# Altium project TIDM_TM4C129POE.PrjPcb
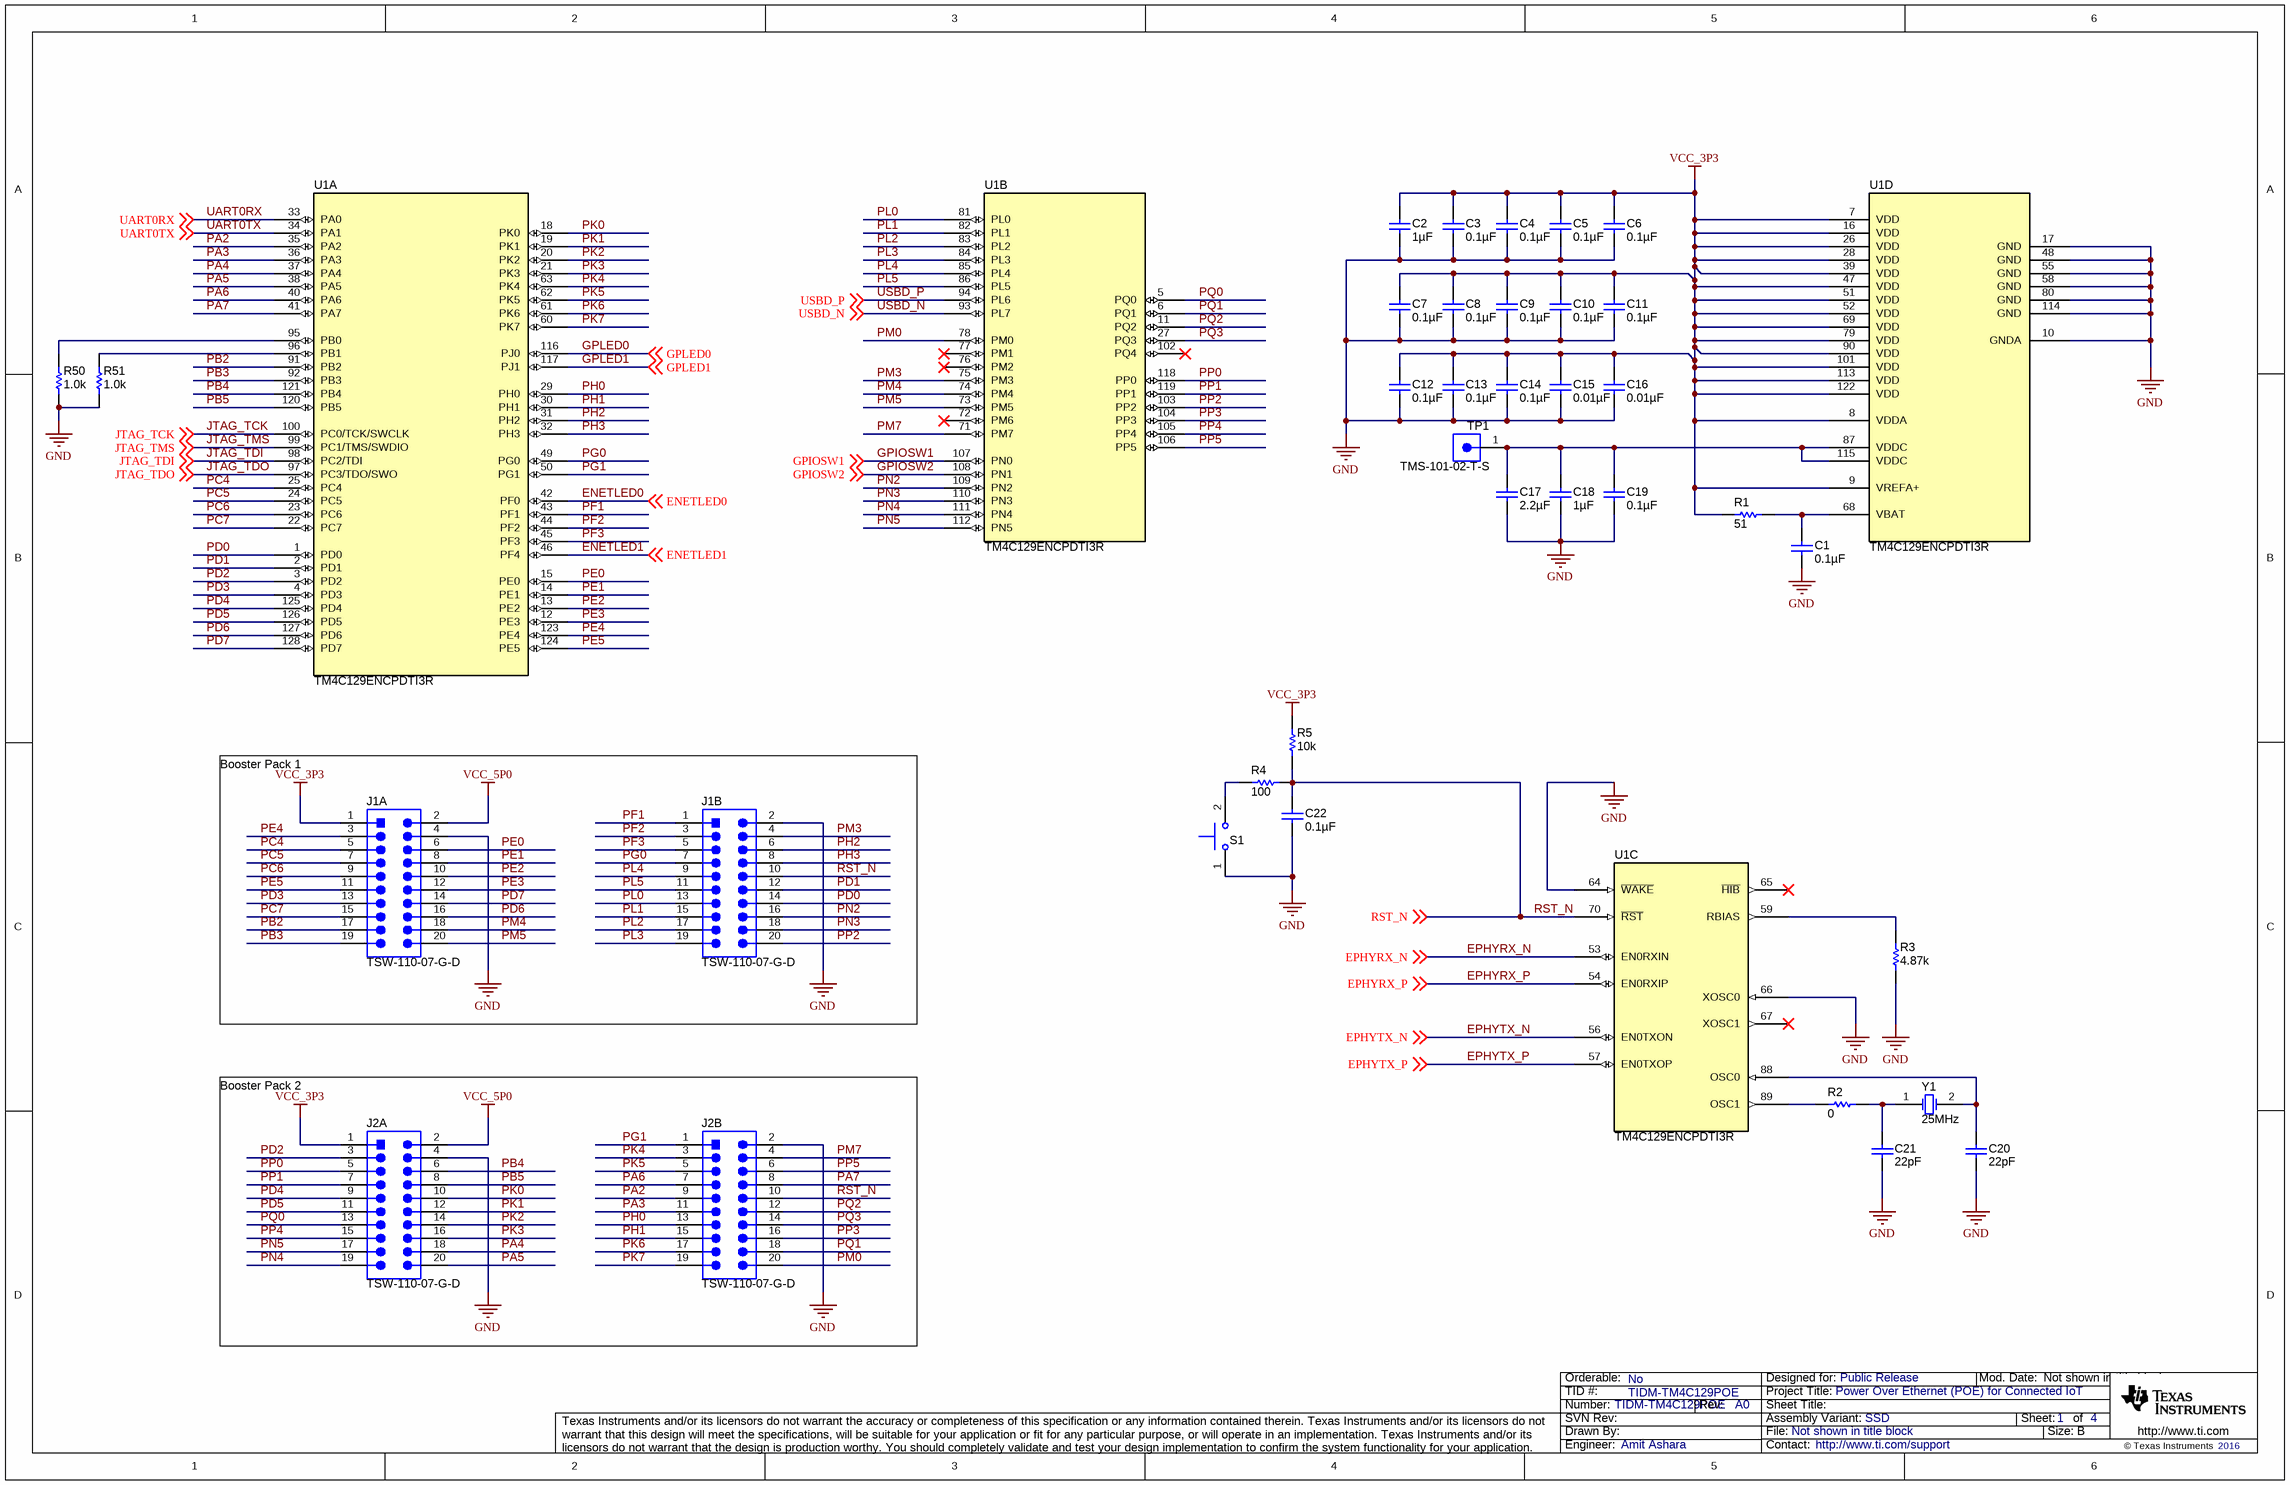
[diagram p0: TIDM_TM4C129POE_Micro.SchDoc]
VariantName: SSD; TID: TIDM-TM4C129POE; TechSupport: http://www.ti.com/support; SCH_Rev: A0; PRJ_Title: Power Over Ethernet (POE) for Connected IoT; PRJ_Number: TIDM-TM4C129POE; PRJ_Engineer: Amit Ashara; PRJ_Customer: Public Release; PCB_Rev: A0; PCB_Layout: Amit Ashara; EVM_Orderable: No; CopyrightYear: 2016
4 sheets, 160 parts. Net scope: global (net labels, ports and power ports of the same name join across sheets).
Board file: TIDM_TM4C129POE.PcbDoc
Sheets:
  TIDM_TM4C129POE_Micro.SchDoc
  TIDM_TM4C129POE_Connector.SchDoc
  TIDM_TM4C129POE_Ethernet.SchDoc
  TIDM_TM4C129POE_PowerStage.SchDoc

## Sheet TIDM_TM4C129POE_Micro.SchDoc
size 431 x 279 mm; Date: Not shown in title block; ApprovedBy: Not shown in title block; CheckedBy: Not shown in title block; Author: Not shown in title block; CompanyName: Not shown in title block; Engineer: Not shown in title block; Organization: Not shown in title block; Address1: Not shown in title block; Address2: Not shown in title block; Address3: Not shown in title block; Address4: Not shown in title block; DocumentNumber: 1; Revision: Use project parameter SCH_Rev; SheetNumber: 1; SheetTotal: 4; PageSetup: Record=PageOptions¦CenterHorizontal=True¦CenterVertical=True¦PrintScale=1.00¦XCorrection=1.00¦YCorrection=1.00¦PrintKind=0¦BorderSize=5000000¦LeftOffset=0¦BottomOffset=0¦Orientation=2¦PaperLength=1000¦PaperWidth=1000¦Scale=100¦PaperSource=15¦PrintQuality=600¦MediaType=1¦DitherType=10¦PaperKind=Letter¦PrintScaleMode=1

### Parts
C1  ValueDisplayed: 0.1µF  [0402]  (hidden comment: GRM155R71C104KA88D)
C2  ValueDisplayed: 1µF  [0402]  (hidden comment: C1005X5R1C105K050BC)
C3  ValueDisplayed: 0.1µF  [0402]  (hidden comment: GRM155R71C104KA88D)
C4  ValueDisplayed: 0.1µF  [0402]  (hidden comment: GRM155R71C104KA88D)
C5  ValueDisplayed: 0.1µF  [0402]  (hidden comment: GRM155R71C104KA88D)
C6  ValueDisplayed: 0.1µF  [0402]  (hidden comment: GRM155R71C104KA88D)
C7  ValueDisplayed: 0.1µF  [0402]  (hidden comment: GRM155R71C104KA88D)
C8  ValueDisplayed: 0.1µF  [0402]  (hidden comment: GRM155R71C104KA88D)
C9  ValueDisplayed: 0.1µF  [0402]  (hidden comment: GRM155R71C104KA88D)
C10  ValueDisplayed: 0.1µF  [0402]  (hidden comment: GRM155R71C104KA88D)
C11  ValueDisplayed: 0.1µF  [0402]  (hidden comment: GRM155R71C104KA88D)
C12  ValueDisplayed: 0.1µF  [0402]  (hidden comment: GRM155R71C104KA88D)
C13  ValueDisplayed: 0.1µF  [0402]  (hidden comment: GRM155R71C104KA88D)
C14  ValueDisplayed: 0.1µF  [0402]  (hidden comment: GRM155R71C104KA88D)
C15  ValueDisplayed: 0.01µF  [0402]  (hidden comment: GRM155R71C103KA01D)
C16  ValueDisplayed: 0.01µF  [0402]  (hidden comment: GRM155R71C103KA01D)
C17  ValueDisplayed: 2.2µF  [0402]  (hidden comment: GRM155R61C225KE11D)
C18  ValueDisplayed: 1µF  [0402]  (hidden comment: C1005X5R1C105K050BC)
C19  ValueDisplayed: 0.1µF  [0402]  (hidden comment: GRM155R71C104KA88D)
C20  ValueDisplayed: 22pF  [0402]  (hidden comment: C1005C0G1H220J050BA)
C21  ValueDisplayed: 22pF  [0402]  (hidden comment: C1005C0G1H220J050BA)
C22  ValueDisplayed: 0.1µF  [0603]  (hidden comment: C0603C104J3RAC)
J1A  TSW-110-07-G-D  [TSW-110-07-G-D]
J1B  TSW-110-07-G-D  [TSW-110-07-G-D]
J2A  TSW-110-07-G-D  [TSW-110-07-G-D]
J2B  TSW-110-07-G-D  [TSW-110-07-G-D]
R1  ValueDisplayed: 51  [0603]  (hidden comment: CRCW060351R0JNEA)
R2  ValueDisplayed: 0  [0402]  (hidden comment: ERJ-2GE0R00X)
R3  ValueDisplayed: 4.87k  [0603]  (hidden comment: CRCW06034K87FKEA)
R4  ValueDisplayed: 100  [0402]  (hidden comment: CRCW0402100RJNED)
R5  ValueDisplayed: 10k  [0402]  (hidden comment: CRCW040210K0JNED)
R50  ValueDisplayed: 1.0k  [0402]  (hidden comment: CRCW04021K00JNED)
R51  ValueDisplayed: 1.0k  [0402]  (hidden comment: CRCW04021K00JNED)
S1  SKRKAEE010  [SW_SKRKAEE010]  (value not drawn)
TP1  TMS-101-02-T-S  [SAMTEC_TMS-101-02-T-S]
U1  TM4C129ENCPDTI3R  [PDT0128A_N]  (parts A,B,C,D of 4)
Y1  Frequency: 25MHz  [NDK_NX5032GA]  (hidden comment: NX5032GA-25.000M-STD-CSK-4)

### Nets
GND: C1.2 C2.2 C3.2 C4.2 C5.2 C6.2 C7.2 C8.2 C9.2 C10.2 C11.2 C12.2 C13.2 C14.2 C15.2 C16.2 C17.2 C18.2 C19.2 C20.2 C21.2 C22.2 J1A.4 J1B.2 J2A.4 J2B.2 R3.1 R50.1 R51.1 S1.1 U1.10(GNDA) U1.17(GND) U1.48(GND) U1.55(GND) U1.58(GND) U1.64(~{WAKE}) U1.66(XOSC0) U1.80(GND) U1.114(GND)
VCC_3P3: C2.1 C3.1 C4.1 C5.1 C6.1 C7.1 C8.1 C9.1 C10.1 C11.1 C12.1 C13.1 C14.1 C15.1 C16.1 J1A.1 J2A.1 R1.1 R5.2 U1.7(VDD) U1.8(VDDA) U1.9(VREFA+) U1.16(VDD) U1.26(VDD) U1.28(VDD) U1.39(VDD) U1.47(VDD) U1.51(VDD) U1.52(VDD) U1.69(VDD) U1.79(VDD) U1.90(VDD) U1.101(VDD) U1.113(VDD) U1.122(VDD)
VCC_5P0: J1A.2 J2A.2
ENETLED0: U1.42(PF0) ; off-sheet ENETLED0
ENETLED1: U1.46(PF4) ; off-sheet ENETLED1
EPHYRX_N: U1.53(EN0RXIN) ; off-sheet EPHYRX_N
EPHYRX_P: U1.54(EN0RXIP) ; off-sheet EPHYRX_P
EPHYTX_N: U1.56(EN0TXON) ; off-sheet EPHYTX_N
EPHYTX_P: U1.57(EN0TXOP) ; off-sheet EPHYTX_P
GPIOSW1: U1.107(PN0) ; off-sheet GPIOSW1
GPIOSW2: U1.108(PN1) ; off-sheet GPIOSW2
GPLED0: U1.116(PJ0) ; off-sheet GPLED0
GPLED1: U1.117(PJ1) ; off-sheet GPLED1
JTAG_TCK: U1.100(PC0/TCK/SWCLK) ; off-sheet JTAG_TCK
JTAG_TDI: U1.98(PC2/TDI) ; off-sheet JTAG_TDI
JTAG_TDO: U1.97(PC3/TDO/SWO) ; off-sheet JTAG_TDO
JTAG_TMS: U1.99(PC1/TMS/SWDIO) ; off-sheet JTAG_TMS
PA2: J2B.9 U1.35(PA2)
PA3: J2B.11 U1.36(PA3)
PA4: J2A.18 U1.37(PA4)
PA5: J2A.20 U1.38(PA5)
PA6: J2B.7 U1.40(PA6)
PA7: J2B.8 U1.41(PA7)
PB2: J1A.17 U1.91(PB2)
PB3: J1A.19 U1.92(PB3)
PB4: J2A.6 U1.121(PB4)
PB5: J2A.8 U1.120(PB5)
PC4: J1A.5 U1.25(PC4)
PC5: J1A.7 U1.24(PC5)
PC6: J1A.9 U1.23(PC6)
PC7: J1A.15 U1.22(PC7)
PD0: J1B.14 U1.1(PD0)
PD1: J1B.12 U1.2(PD1)
PD2: J2A.3 U1.3(PD2)
PD3: J1A.13 U1.4(PD3)
PD4: J2A.9 U1.125(PD4)
PD5: J2A.11 U1.126(PD5)
PD6: J1A.16 U1.127(PD6)
PD7: J1A.14 U1.128(PD7)
PE0: J1A.6 U1.15(PE0)
PE1: J1A.8 U1.14(PE1)
PE2: J1A.10 U1.13(PE2)
PE3: J1A.12 U1.12(PE3)
PE4: J1A.3 U1.123(PE4)
PE5: J1A.11 U1.124(PE5)
PF1: J1B.1 U1.43(PF1)
PF2: J1B.3 U1.44(PF2)
PF3: J1B.5 U1.45(PF3)
PG0: J1B.7 U1.49(PG0)
PG1: J2B.1 U1.50(PG1)
PH0: J2B.13 U1.29(PH0)
PH1: J2B.15 U1.30(PH1)
PH2: J1B.6 U1.31(PH2)
PH3: J1B.8 U1.32(PH3)
PK0: J2A.10 U1.18(PK0)
PK1: J2A.12 U1.19(PK1)
PK2: J2A.14 U1.20(PK2)
PK3: J2A.16 U1.21(PK3)
PK4: J2B.3 U1.63(PK4)
PK5: J2B.5 U1.62(PK5)
PK6: J2B.17 U1.61(PK6)
PK7: J2B.19 U1.60(PK7)
PL0: J1B.13 U1.81(PL0)
PL1: J1B.15 U1.82(PL1)
PL2: J1B.17 U1.83(PL2)
PL3: J1B.19 U1.84(PL3)
PL4: J1B.9 U1.85(PL4)
PL5: J1B.11 U1.86(PL5)
PM0: J2B.20 U1.78(PM0)
PM3: J1B.4 U1.75(PM3)
PM4: J1A.18 U1.74(PM4)
PM5: J1A.20 U1.73(PM5)
PM7: J2B.4 U1.71(PM7)
PN2: J1B.16 U1.109(PN2)
PN3: J1B.18 U1.110(PN3)
PN4: J2A.19 U1.111(PN4)
PN5: J2A.17 U1.112(PN5)
PP0: J2A.5 U1.118(PP0)
PP1: J2A.7 U1.119(PP1)
PP2: J1B.20 U1.103(PP2)
PP3: J2B.16 U1.104(PP3)
PP4: J2A.15 U1.105(PP4)
PP5: J2B.6 U1.106(PP5)
PQ0: J2A.13 U1.5(PQ0)
PQ1: J2B.18 U1.6(PQ1)
PQ2: J2B.12 U1.11(PQ2)
PQ3: J2B.14 U1.27(PQ3)
RST_N: C22.1 J1B.10 J2B.10 R4.1 R5.1 U1.70(~{RST}) ; off-sheet RST_N
UART0RX: U1.33(PA0) ; off-sheet UART0RX
UART0TX: U1.34(PA1) ; off-sheet UART0TX
USBD_N: U1.93(PL7) ; off-sheet USBD_N
USBD_P: U1.94(PL6) ; off-sheet USBD_P
NetC1_1: C1.1 R1.2 U1.68(VBAT)
NetC17_1: C17.1 C18.1 C19.1 TP1.1 U1.87(VDDC) U1.115(VDDC)
NetC20_1: C20.1 U1.88(OSC0) Y1.2(OSC2)
NetC21_1: C21.1 R2.2 Y1.1(OSC1)
NetR2_1: R2.1 U1.89(OSC1)
NetR3_2: R3.2 U1.59(RBIAS)
NetR4_2: R4.2 S1.2
NetR50_2: R50.2 U1.95(PB0)
NetR51_2: R51.2 U1.96(PB1)

Not connected (* = marked no-connect by the designer): U1 65(~{HIB})* 67(XOSC1)* 72(PM6)* 76(PM2)* 77(PM1)* 102(PQ4)*

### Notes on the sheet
- Booster Pack 1
- Booster Pack 2

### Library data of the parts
C1 C3-C14 C19 = GRM155R71C104KA88D: CAP, CERM, 0.1 µF, 16 V, +/- 10%, X7R, 0402; Manufacturer: MuRata; Polarized: N; CompType: Capacitor; Value: 0.1uF; U/M: EA; Cap_F: 0.0000001; Tolerance_%: 10; Value1: Unknown; VDC_V: 16; Value2: 16V; TaMin_C: -55; TaMax_C: 125; AEC Category: Q200
C2 C18 = C1005X5R1C105K050BC: CAP, CERM, 1 µF, 16 V, +/- 10%, X5R, 0402; Manufacturer: TDK; Polarized: N; CompType: Capacitor; Value: 1uF; U/M: EA; Cap_F: 0.000001; Tolerance_%: 10; Value1: Unknown; VDC_V: 16; Value2: 16V; TaMin_C: -55; TaMax_C: 85; AEC Category: Q200
C15 C16 = GRM155R71C103KA01D: CAP, CERM, 0.01 µF, 16 V, +/- 10%, X7R, 0402; Manufacturer: MuRata; Polarized: N; CompType: Capacitor; Value: 0.01uF; U/M: EA; Cap_F: 0.00000001; Tolerance_%: 10; Value1: Unknown; VDC_V: 16; Value2: 16V; TaMin_C: -55; TaMax_C: 125; AEC Category: Q200
C17 = GRM155R61C225KE11D: CAP, CERM, 2.2 µF, 16 V, +/- 10%, X5R, 0402; Manufacturer: MuRata; Polarized: N; CompType: Capacitor; Value: 2.2uF; U/M: EA; Cap_F: 0.0000022; Tolerance_%: 10; Value1: Unknown; VDC_V: 16; Value2: 16V; TaMin_C: -55; TaMax_C: 85; AEC Category: Q200
C20 C21 = C1005C0G1H220J050BA: CAP, CERM, 22 pF, 50 V, +/- 5%, C0G/NP0, 0402; Manufacturer: TDK; Polarized: N; CompType: Capacitor; Value: 22pF; U/M: EA; Cap_F: 0.000000000022; Tolerance_%: 5; Value1: Unknown; VDC_V: 50; Value2: 50V; TaMin_C: -55; TaMax_C: 125; AEC Category: Q200
C22 = C0603C104J3RAC: CAP, CERM, 0.1 µF, 25 V, +/- 5%, X7R, 0603; Manufacturer: Kemet; Polarized: N; CompType: Capacitor; Value: 0.1uF; U/M: EA; Cap_F: 0.0000001; Tolerance_%: 5; Value1: Unknown; VDC_V: 25; Value2: 25V; TaMin_C: -55; TaMax_C: 125; AEC Category: Q200
J1A J1B J2A J2B = TSW-110-07-G-D: Header, 100mil, 10x2, Gold, TH; Manufacturer: Samtec; SymbolCreator: a0412235; Pitch_mm: 2.54; Gender: Male; Shrouded: N; Row_Count: 2; Current_A: 6.3; Voltage_V: 550; Cert_CSA: Y
R1 = CRCW060351R0JNEA: RES, 51, 5%, 0.1 W, 0603; Manufacturer: Vishay-Dale; CompType: Resistor; Value: 51; Value_Code: 51R0; Tolerance_%: 5; Power_W: 0.1; Value2: 0.1W; VDC_V: 75; TempCo: 200 ppm/C; EIA_Code: E24; U/M: EA; AEC Category: Q200
R2 = ERJ-2GE0R00X: RES, 0, 5%, 0.063 W, 0402; Manufacturer: Panasonic; CompType: Resistor; Value: 0; Value_Code: 0000; Tolerance_%: 5; Power_W: 0.063; Value2: 0.063W; VDC_V: 50; TempCo: 600 ppm/C; EIA_Code: E24; U/M: EA; AEC Category: Q200
R3 = CRCW06034K87FKEA: RES, 4.87 k, 1%, 0.1 W, 0603; Manufacturer: Vishay-Dale; CompType: Resistor; Value: 4.87k; Res_ohm: 4870; Value_Code: 4k87; Tolerance_%: 1; Power_W: 0.1; Value2: 0.1W; VDC_V: 75; TempCo: 100 ppm/C; EIA_Code: E96; U/M: EA; AEC Category: Q200
R4 = CRCW0402100RJNED: RES, 100, 5%, 0.063 W, 0402; Manufacturer: Vishay-Dale; CompType: Resistor; Value: 100; Value_Code: 100R; Tolerance_%: 5; Power_W: 0.063; Value2: 0.063W; VDC_V: 50; TempCo: 200 ppm/C; EIA_Code: E24; U/M: EA; AEC Category: Q200
R5 = CRCW040210K0JNED: RES, 10 k, 5%, 0.063 W, 0402; Manufacturer: Vishay-Dale; CompType: Resistor; Value: 10k; Res_ohm: 10000; Value_Code: 10k0; Tolerance_%: 5; Power_W: 0.063; Value2: 0.063W; VDC_V: 50; TempCo: 200 ppm/C; EIA_Code: E24; U/M: EA; AEC Category: Q200
R50 R51 = CRCW04021K00JNED: RES, 1.0 k, 5%, 0.063 W, 0402; Manufacturer: Vishay-Dale; CompType: Resistor; Value: 1.0k; Res_ohm: 1000; Value_Code: 1k00; Tolerance_%: 5; Power_W: 0.063; Value2: 0.063W; VDC_V: 50; TempCo: 200 ppm/C; EIA_Code: E24; U/M: EA; AEC Category: Q200
S1 = SKRKAEE010: Switch, Push Button, SMD; Manufacturer: Alps; SymbolCreator: a0412235; Circuit: SPST-NO; VDC_V: 12; SwitchFunction: Off-Mom; PositionCount: 1; CurrentRating_mA: 50
TP1 = TMS-101-02-T-S: Header, 1x1, Tin, TH; Manufacturer: Samtec; SymbolCreator: a0412235
U1 = TM4C129ENCPDTI3R: Tiva C Series Microcontroller, PDT0128A; Manufacturer: Texas Instruments; SymbolCreator: a0411947; CompType: IC; U/M: EA
Y1 = NX5032GA-25.000M-STD-CSK-4: Crystal, 25MHz,  SMD; Manufacturer: NDK; SymbolCreator: a0412235; U/M: EA; TaMin_C: -40; TaMax_C: 150; Frequency Stability: ±30ppm

## Sheet TIDM_TM4C129POE_Connector.SchDoc
size 431 x 279 mm; Date: Not shown in title block; ApprovedBy: Not shown in title block; CheckedBy: Not shown in title block; Author: Not shown in title block; CompanyName: Not shown in title block; Engineer: Not shown in title block; Organization: Not shown in title block; Address1: Not shown in title block; Address2: Not shown in title block; Address3: Not shown in title block; Address4: Not shown in title block; DocumentNumber: 1; Revision: Use project parameter SCH_Rev; SheetNumber: 2; SheetTotal: 4; PageSetup: Record=PageOptions¦CenterHorizontal=True¦CenterVertical=True¦PrintScale=1.00¦XCorrection=1.00¦YCorrection=1.00¦PrintKind=0¦BorderSize=5000000¦LeftOffset=0¦BottomOffset=0¦Orientation=2¦PaperLength=1000¦PaperWidth=1000¦Scale=100¦PaperSource=15¦PrintQuality=600¦MediaType=1¦DitherType=10¦PaperKind=Letter¦PrintScaleMode=1
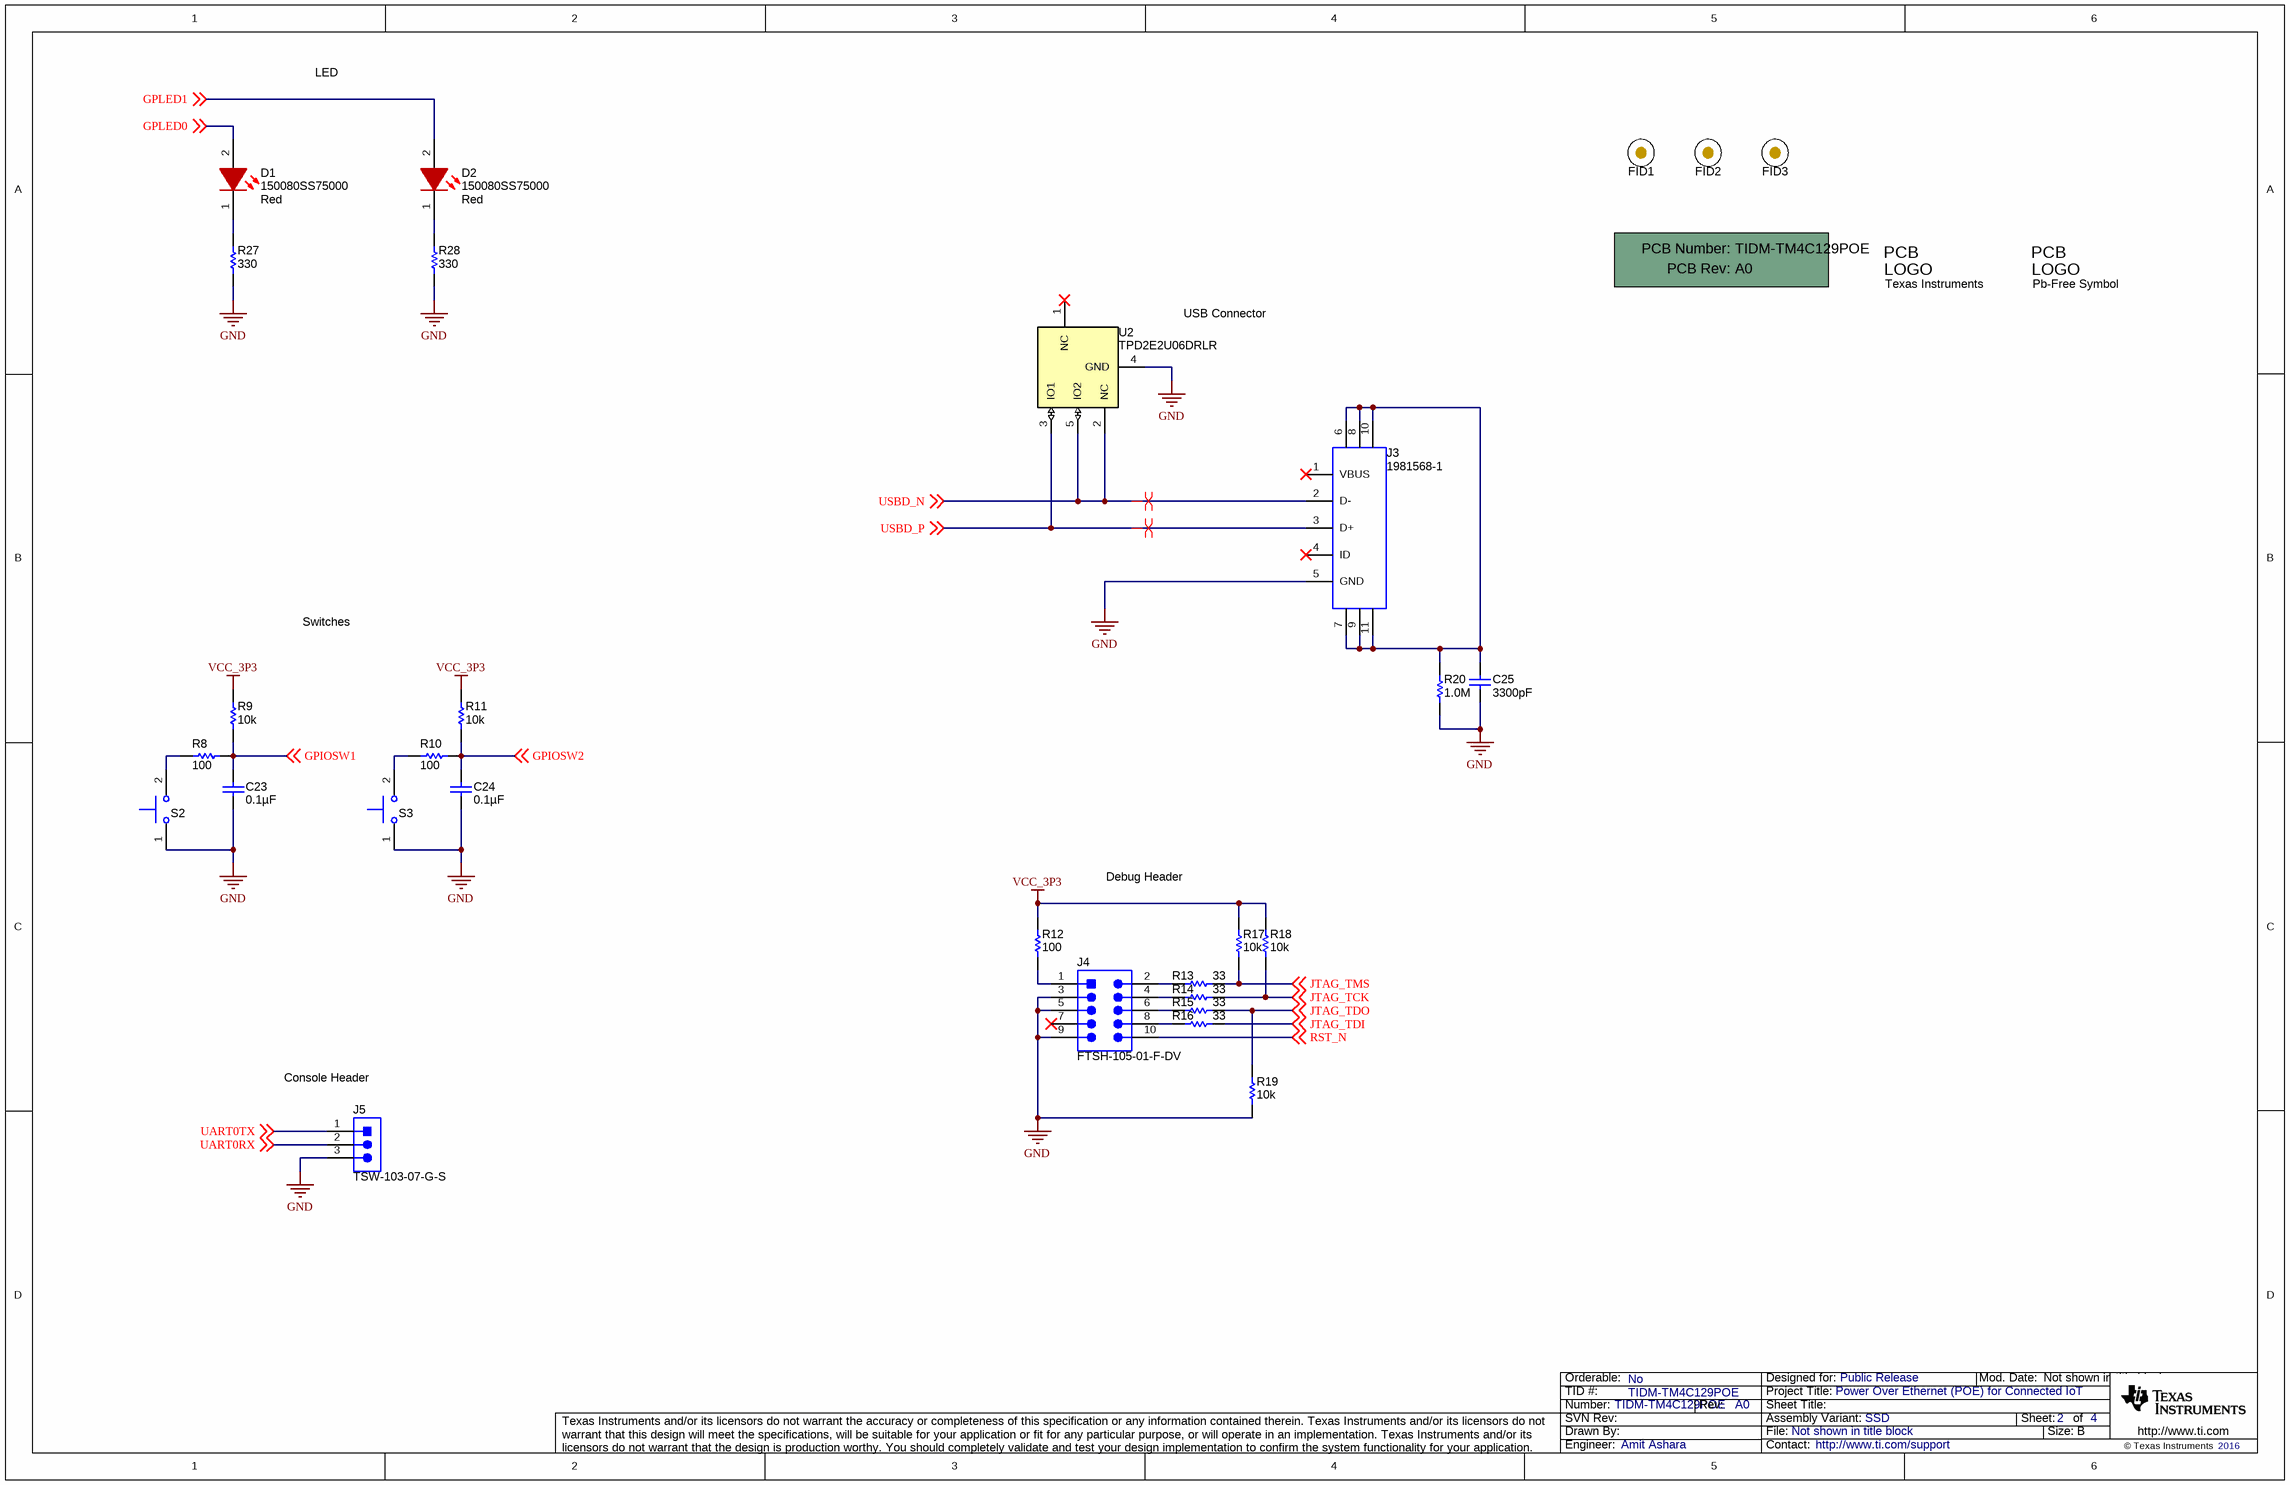
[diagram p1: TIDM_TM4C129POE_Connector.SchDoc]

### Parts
!PCB  Printed Circuit Board  (value not drawn)  (mechanical)
C23  ValueDisplayed: 0.1µF  [0603]  (hidden comment: C0603C104J3RAC)
C24  ValueDisplayed: 0.1µF  [0603]  (hidden comment: C0603C104J3RAC)
C25  ValueDisplayed: 3300pF  [0603]  (hidden comment: C0603X332K5RACTU)
D1  150080SS75000  value Red  [WL-SMCW_RED_0805]
D2  150080SS75000  value Red  [WL-SMCW_RED_0805]
FID1  Fiducial  [Fiducial10-20]  (value not drawn)
FID2  Fiducial  [Fiducial10-20]  (value not drawn)
FID3  Fiducial  [Fiducial10-20]  (value not drawn)
J3  1981568-1  [TE_1981568-1]
J4  FTSH-105-01-F-DV  [Samtec_FTSH-105-01-x-DV]
J5  TSW-103-07-G-S  [TSW-103-07-G-S]
Logo1  Texas Instruments  [TI_Stacked_Overlay_Small]  (no BOM)
Logo2  Pb-Free Symbol  [Pb-Free_Overlay_Small]  (no BOM)
R8  ValueDisplayed: 100  [0402]  (hidden comment: CRCW0402100RJNED)
R9  ValueDisplayed: 10k  [0402]  (hidden comment: CRCW040210K0JNED)
R10  ValueDisplayed: 100  [0402]  (hidden comment: CRCW0402100RJNED)
R11  ValueDisplayed: 10k  [0402]  (hidden comment: CRCW040210K0JNED)
R12  ValueDisplayed: 100  [0603]  (hidden comment: CRCW0603100RJNEA)
R13  ValueDisplayed: 33  [0603]  (hidden comment: CRCW060333R0JNEA)
R14  ValueDisplayed: 33  [0603]  (hidden comment: CRCW060333R0JNEA)
R15  ValueDisplayed: 33  [0603]  (hidden comment: CRCW060333R0JNEA)
R16  ValueDisplayed: 33  [0603]  (hidden comment: CRCW060333R0JNEA)
R17  ValueDisplayed: 10k  [0603]  (hidden comment: CRCW060310K0JNEA)
R18  ValueDisplayed: 10k  [0603]  (hidden comment: CRCW060310K0JNEA)
R19  ValueDisplayed: 10k  [0603]  (hidden comment: CRCW060310K0JNEA)
R20  ValueDisplayed: 1.0M  [0603]  (hidden comment: CRCW06031M00JNEA)
R27  ValueDisplayed: 330  [0603]  (hidden comment: RC0603JR-07330RL)
R28  ValueDisplayed: 330  [0603]  (hidden comment: RC0603JR-07330RL)
S2  SKRKAEE010  [SW_SKRKAEE010]  (value not drawn)
S3  SKRKAEE010  [SW_SKRKAEE010]  (value not drawn)
U2  TPD2E2U06DRLR  [DRL0005A]

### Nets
GND: C23.2 C24.2 C25.2 J3.5(GND) J4.3 J4.5 J4.9 J5.3 R19.1 R20.1 R27.2 R28.2 S2.1 S3.1 U2.4(GND)
VCC_3P3: R9.2 R11.2 R12.1 R17.2 R18.2
GPIOSW1: C23.1 R8.1 R9.1 ; off-sheet GPIOSW1
GPIOSW2: C24.1 R10.1 R11.1 ; off-sheet GPIOSW2
GPLED0: D1.2(A) ; off-sheet GPLED0
GPLED1: D2.2(A) ; off-sheet GPLED1
JTAG_TCK: R14.2 R18.1 ; off-sheet JTAG_TCK
JTAG_TDI: R16.2 ; off-sheet JTAG_TDI
JTAG_TDO: R15.2 R19.2 ; off-sheet JTAG_TDO
JTAG_TMS: R13.2 R17.1 ; off-sheet JTAG_TMS
RST_N: J4.10 ; off-sheet RST_N
UART0RX: J5.2 ; off-sheet UART0RX
UART0TX: J5.1 ; off-sheet UART0TX
USBD_N: J3.2(D-) U2.2(NC) U2.5(IO2) ; off-sheet USBD_N
USBD_P: J3.3(D+) U2.3(IO1) ; off-sheet USBD_P
NetC25_1: C25.1 J3.6 J3.7 J3.8 J3.9 J3.10 J3.11 R20.2
NetD1_1: D1.1(K) R27.1
NetD2_1: D2.1(K) R28.1
NetJ4_1: J4.1 R12.2
NetJ4_2: J4.2 R13.1
NetJ4_4: J4.4 R14.1
NetJ4_6: J4.6 R15.1
NetJ4_8: J4.8 R16.1
NetR8_2: R8.2 S2.2
NetR10_2: R10.2 S3.2

Not connected (* = marked no-connect by the designer): J3 1(VBUS)* 4(ID)*; J4 7*; U2 1(NC)*

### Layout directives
differential pair: USBD_N, USBD_P

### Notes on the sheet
- LED
- USB Connector
- Switches
- Debug Header
- (near J5) Console Header

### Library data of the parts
!PCB = PCB: Manufacturer: Any; PartNumber: TIDM-TM4C129POE; SymbolCreator: a0412235
C23 C24 = C0603C104J3RAC: as C22 on sheet TIDM_TM4C129POE_Micro
C25 = C0603X332K5RACTU: CAP, CERM, 3300 pF, 50 V, +/- 10%, X7R, 0603; Manufacturer: Kemet; Polarized: N; CompType: Capacitor; Value: 3300pF; U/M: EA; Cap_F: 0.0000000033; Tolerance_%: 10; Value1: Unknown; VDC_V: 50; Value2: 50V; TaMin_C: -55; TaMax_C: 125; AEC Category: Q200
D1 D2 = 150080SS75000: LED, Red, SMD; Manufacturer: Wurth Elektronik; SymbolCreator: Altium; Type: AlInGaP; Vf_V: 1.9; Value2: 1.9V; Io_A: 0.03; Vr_V: 5; Ir_A: 2.5e-005; Tjmax_C: 85; Power_TotalModule: 0.072; Value1: 0.072W; Angle: 140; U/M: EA
FID1-FID3 = Fiducial: Fiducial mark.  There is nothing to buy or mount.; SymbolCreator: codlsc
J3 = 1981568-1: Connector, Receptacle, Micro-USB Type B, R/A, Bottom Mount SMT; Manufacturer: TE Connectivity; SymbolCreator: a0411947
J4 = FTSH-105-01-F-DV: Header, 1.27mm, 5x2, Gold, Black, SMT; Manufacturer: Samtec; SymbolCreator: a0412235; Pitch_mm: 1.27; Gender: Male; Row_Count: 2; Current_A: 3.3; Cert_CSA: Y
J5 = TSW-103-07-G-S: Header, 100mil, 3x1, Gold, TH; Manufacturer: Samtec; SymbolCreator: a0799628; Pitch_mm: 2.54; Gender: Male; Shrouded: N; Row_Count: 1; Current_A: 6.3; Voltage_V: 550; Cert_CSA: Y
Logo1 = TI_Logo: Texas Instrument Corporate Signature; SymbolCreator: codlsc
Logo2 = Pb-Free: SymbolCreator: a0412235
R8 R10 = CRCW0402100RJNED: as R4 on sheet TIDM_TM4C129POE_Micro
R9 R11 = CRCW040210K0JNED: as R5 on sheet TIDM_TM4C129POE_Micro
R12 = CRCW0603100RJNEA: RES, 100, 5%, 0.1 W, 0603; Manufacturer: Vishay-Dale; CompType: Resistor; Value: 100; Value_Code: 100R; Tolerance_%: 5; Power_W: 0.1; Value2: 0.1W; VDC_V: 75; TempCo: 200 ppm/C; EIA_Code: E24; U/M: EA; AEC Category: Q200
R13-R16 = CRCW060333R0JNEA: RES, 33, 5%, 0.1 W, 0603; Manufacturer: Vishay-Dale; CompType: Resistor; Value: 33; Value_Code: 33R0; Tolerance_%: 5; Power_W: 0.1; Value2: 0.1W; VDC_V: 75; TempCo: 200 ppm/C; EIA_Code: E24; U/M: EA; AEC Category: Q200
R17-R19 = CRCW060310K0JNEA: RES, 10 k, 5%, 0.1 W, 0603; Manufacturer: Vishay-Dale; CompType: Resistor; Value: 10k; Res_ohm: 10000; Value_Code: 10k0; Tolerance_%: 5; Power_W: 0.1; Value2: 0.1W; VDC_V: 75; TempCo: 200 ppm/C; EIA_Code: E24; U/M: EA; AEC Category: Q200
R20 = CRCW06031M00JNEA: RES, 1.0 M, 5%, 0.1 W, 0603; Manufacturer: Vishay-Dale; CompType: Resistor; Value: 1.0Meg; Res_ohm: 1000000; Value_Code: 1M00; Tolerance_%: 5; Power_W: 0.1; Value2: 0.1W; VDC_V: 75; TempCo: 200 ppm/C; EIA_Code: E24; U/M: EA; AEC Category: Q200
R27 R28 = RC0603JR-07330RL: RES, 330, 5%, 0.1 W, 0603; Manufacturer: Yageo America; CompType: Resistor; Value: 330; Value_Code: 330R; Tolerance_%: 5; Power_W: 0.1; Value2: 0.1W; VDC_V: 50; TempCo: 100 ppm/C; EIA_Code: E24; U/M: EA; AEC Category: Q200
S2 S3 = SKRKAEE010: as S1 on sheet TIDM_TM4C129POE_Micro
U2 = TPD2E2U06DRLR: DUAL CHANNEL HIGH SPEED ESD PROTECTION DEVICE, DRL0005A; Manufacturer: Texas Instruments; SymbolCreator: a0411947; CompType: IC; U/M: EA

## Sheet TIDM_TM4C129POE_Ethernet.SchDoc
size 431 x 279 mm; Date: Not shown in title block; ApprovedBy: Not shown in title block; CheckedBy: Not shown in title block; Author: Not shown in title block; CompanyName: Not shown in title block; Engineer: Not shown in title block; Organization: Not shown in title block; Address1: Not shown in title block; Address2: Not shown in title block; Address3: Not shown in title block; Address4: Not shown in title block; DocumentNumber: 1; Revision: Use project parameter SCH_Rev; SheetNumber: 3; SheetTotal: 4; PageSetup: Record=PageOptions¦CenterHorizontal=True¦CenterVertical=True¦PrintScale=1.00¦XCorrection=1.00¦YCorrection=1.00¦PrintKind=0¦BorderSize=5000000¦LeftOffset=0¦BottomOffset=0¦Orientation=2¦PaperLength=1000¦PaperWidth=1000¦Scale=100¦PaperSource=15¦PrintQuality=600¦MediaType=1¦DitherType=10¦PaperKind=Letter¦PrintScaleMode=1
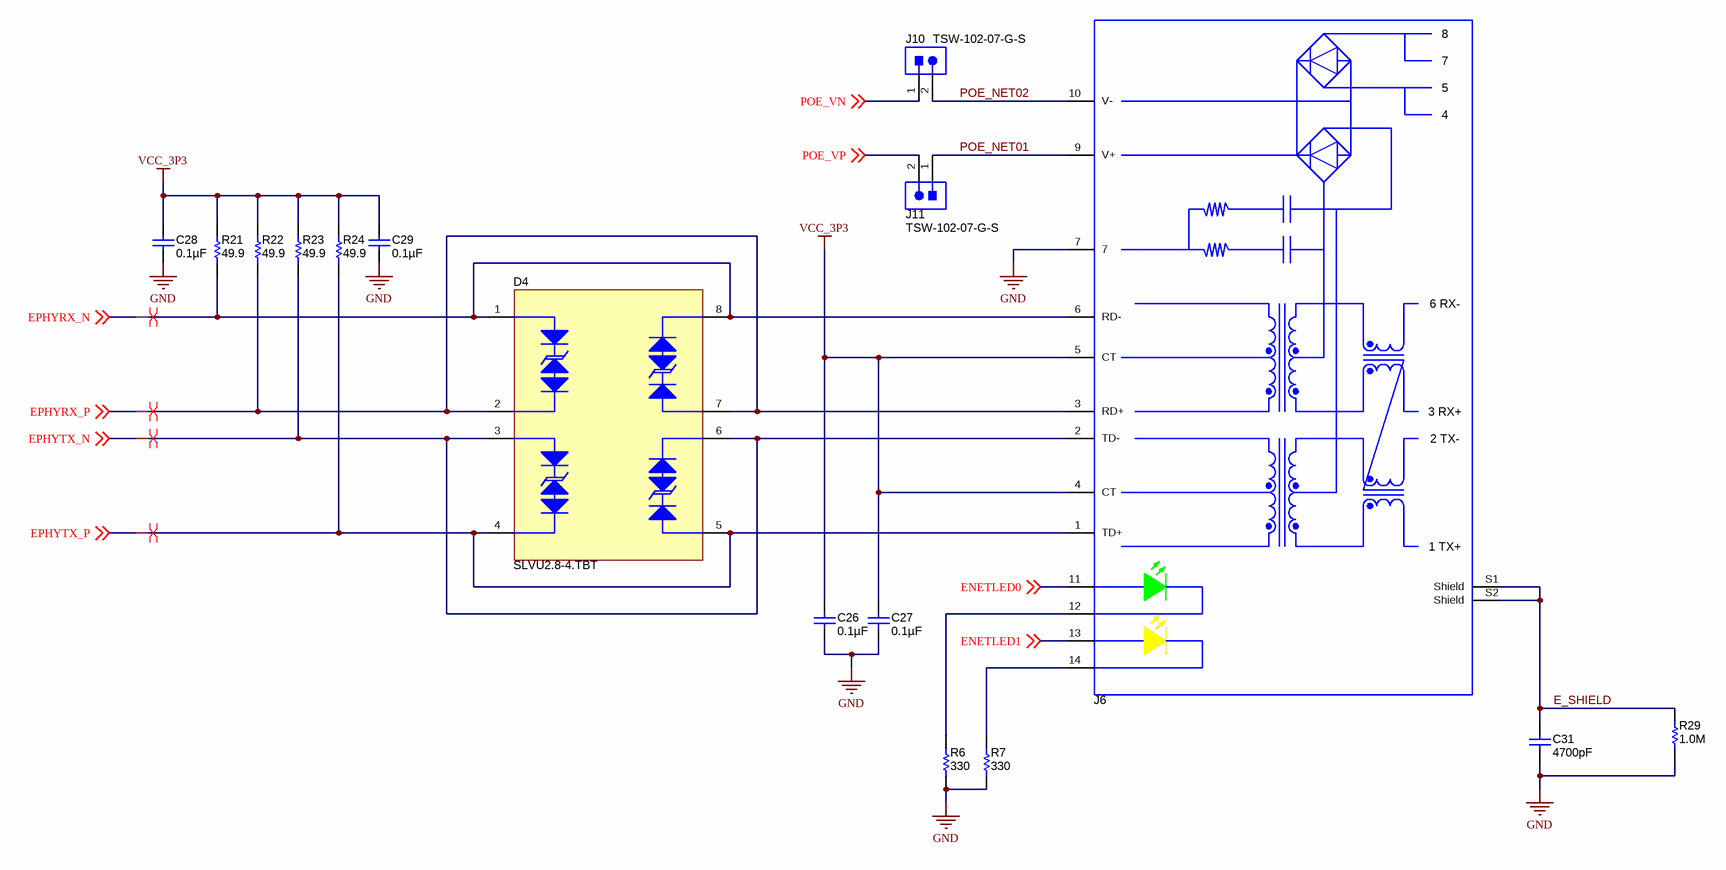
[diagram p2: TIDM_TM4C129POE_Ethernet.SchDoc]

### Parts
C26  ValueDisplayed: 0.1µF  [0402]  (hidden comment: GCM155R71C104KA55D)
C27  ValueDisplayed: 0.1µF  [0402]  (hidden comment: GCM155R71C104KA55D)
C28  ValueDisplayed: 0.1µF  [0402]  (hidden comment: GCM155R71C104KA55D)
C29  ValueDisplayed: 0.1µF  [0402]  (hidden comment: GCM155R71C104KA55D)
C31  ValueDisplayed: 4700pF  [1812]  (hidden comment: 1812GC472KA1)
D4  SLVU2.8-4.TBT  [SO-8]
J6  ARJP11A-MASA-B-A-EMU2  [Abracon_ARJP11A]  (value not drawn)
J10  TSW-102-07-G-S  [TSW-102-07-G-S]
J11  TSW-102-07-G-S  [TSW-102-07-G-S]
R6  ValueDisplayed: 330  [0603]  (hidden comment: RC0603JR-07330RL)
R7  ValueDisplayed: 330  [0603]  (hidden comment: RC0603JR-07330RL)
R21  ValueDisplayed: 49.9  [0402]  (hidden comment: CRCW040249R9FKED)
R22  ValueDisplayed: 49.9  [0402]  (hidden comment: CRCW040249R9FKED)
R23  ValueDisplayed: 49.9  [0402]  (hidden comment: CRCW040249R9FKED)
R24  ValueDisplayed: 49.9  [0402]  (hidden comment: CRCW040249R9FKED)
R29  ValueDisplayed: 1.0M  [1206]  (hidden comment: CRCW12061M00JNEA)

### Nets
GND: C26.2 C27.2 C28.2 C29.2 C31.2 J6.7 R6.2 R7.2 R29.1
VCC_3P3: C26.1 C27.1 C28.1 C29.1 J6.4(CT) J6.5(CT) R21.2 R22.2 R23.2 R24.2
E_SHIELD: C31.1 J6.S1(Shield) J6.S2(Shield) R29.2
ENETLED0: J6.11(LEFT_LED_ANODE) ; off-sheet ENETLED0
ENETLED1: J6.13(RIGHT_LED_ANODE) ; off-sheet ENETLED1
EPHYRX_N: D4.1 D4.8 J6.6(RD-) R21.1 ; off-sheet EPHYRX_N
EPHYRX_P: D4.2 D4.7 J6.3(RD+) R22.1 ; off-sheet EPHYRX_P
EPHYTX_N: D4.3 D4.6 J6.2(TD-) R23.1 ; off-sheet EPHYTX_N
EPHYTX_P: D4.4 D4.5 J6.1(TD+) R24.1 ; off-sheet EPHYTX_P
POE_NET01: J6.9(V+) J11.1
POE_NET02: J6.10(V-) J10.2
POE_VN: J10.1 ; off-sheet POE_VN
POE_VP: J11.2 ; off-sheet POE_VP
NetJ6_12: J6.12(LEFT_LED_CATHODE) R6.1
NetJ6_14: J6.14(RIGHT_LED_CATHODE) R7.1

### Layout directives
differential pair: EPHYRX_N, EPHYRX_P, EPHYTX_N, EPHYTX_P

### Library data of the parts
C26-C29 = GCM155R71C104KA55D: CAP, CERM, 0.1 µF, 16 V, +/- 10%, X7R, 0402; Manufacturer: MuRata; Polarized: N; CompType: Capacitor; Value: 0.1uF; U/M: EA; Cap_F: 0.0000001; Tolerance_%: 10; Value1: Unknown; VDC_V: 16; Value2: 16V; TaMin_C: -55; TaMax_C: 125; AEC Category: Q200
C31 = 1812GC472KA1: CAP, CERM, 4700 pF, 2000 V, +/- 10%, X7R, 1812; Manufacturer: AVX; Polarized: N; CompType: Capacitor; Value: 4700pF; U/M: EA; Cap_F: 0.0000000047; Tolerance_%: 10; Value1: Unknown; VDC_V: 2000; Value2: 2000V; TaMin_C: -55; TaMax_C: 125; AEC Category: Q200
D4 = SLVU2.8-4.TBT: Diode, TVS, Uni, 2.8 V, 400 W, SO-8; Manufacturer: Semtech; SymbolCreator: Altium; U/M: EA; Power_W: 400; Vr_V: 2.8; Value1: 400W; AEC Category: Q101
J6 = ARJP11A-MASA-B-A-EMU2: Connector, RJ-45 with integrated magnetics, Gold, R/A, TH; Manufacturer: Abracon Corporation; SymbolCreator: Altium; Gender: Female
J10 J11 = TSW-102-07-G-S: Header, 100mil, 2x1, Gold, TH; Manufacturer: Samtec; SymbolCreator: a0412235; Pitch_mm: 2.54; Gender: Male; Shrouded: N; Row_Count: 1; Current_A: 6.3; Voltage_V: 550; Cert_CSA: Y
R6 R7 = RC0603JR-07330RL: as R27 on sheet TIDM_TM4C129POE_Connector
R21-R24 = CRCW040249R9FKED: RES, 49.9, 1%, 0.063 W, 0402; Manufacturer: Vishay-Dale; CompType: Resistor; Value: 49.9; Value_Code: 49R9; Tolerance_%: 1; Power_W: 0.063; Value2: 0.063W; VDC_V: 50; TempCo: 100 ppm/C; EIA_Code: E96; U/M: EA; AEC Category: Q200
R29 = CRCW12061M00JNEA: RES, 1.0 M, 5%, 0.25 W, 1206; Manufacturer: Vishay-Dale; CompType: Resistor; Value: 1.0Meg; Res_ohm: 1000000; Value_Code: 1M00; Tolerance_%: 5; Power_W: 0.25; Value2: 0.25W; VDC_V: 200; TempCo: 200 ppm/C; EIA_Code: E24; U/M: EA; AEC Category: Q200

## Sheet TIDM_TM4C129POE_PowerStage.SchDoc
size 431 x 279 mm; Date: Not shown in title block; ApprovedBy: Not shown in title block; CheckedBy: Not shown in title block; Author: Not shown in title block; CompanyName: Not shown in title block; Engineer: Not shown in title block; Organization: Not shown in title block; Address1: Not shown in title block; Address2: Not shown in title block; Address3: Not shown in title block; Address4: Not shown in title block; DocumentNumber: 1; Revision: Use project parameter SCH_Rev; SheetNumber: 4; SheetTotal: 4; PageSetup: Record=PageOptions¦CenterHorizontal=True¦CenterVertical=True¦PrintScale=1.00¦XCorrection=1.00¦YCorrection=1.00¦PrintKind=0¦BorderSize=5000000¦LeftOffset=0¦BottomOffset=0¦Orientation=2¦PaperLength=1000¦PaperWidth=1000¦Scale=100¦PaperSource=15¦PrintQuality=600¦MediaType=1¦DitherType=10¦PaperKind=Letter¦PrintScaleMode=1
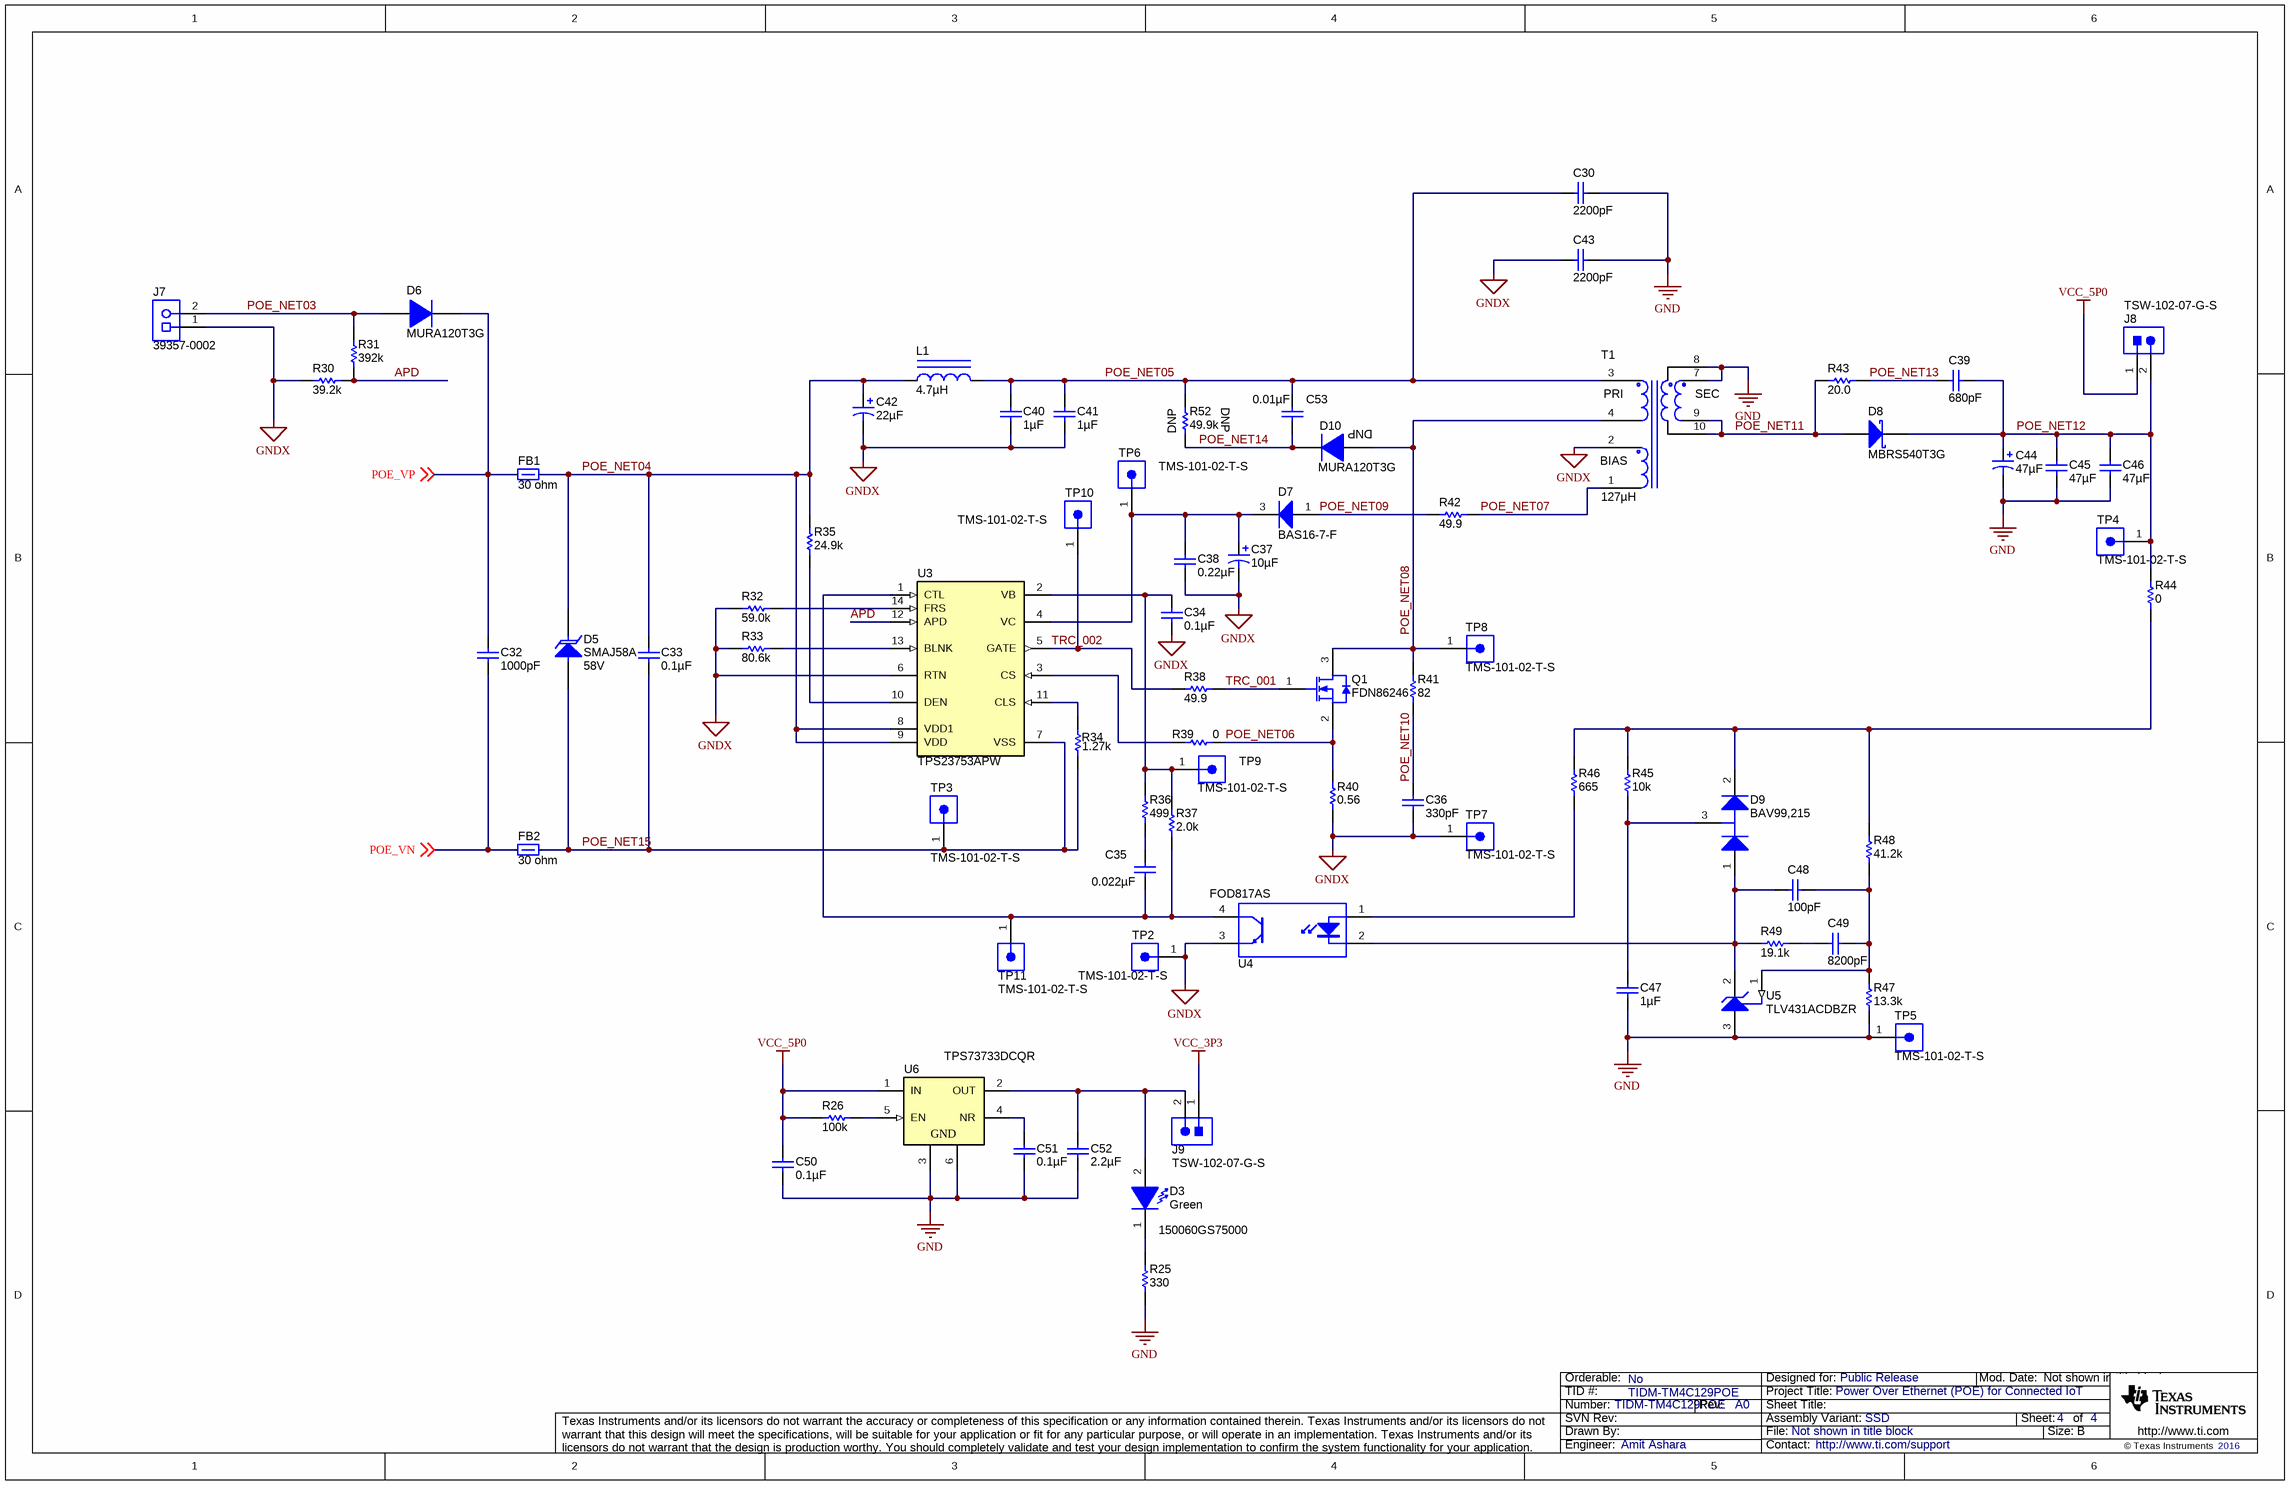
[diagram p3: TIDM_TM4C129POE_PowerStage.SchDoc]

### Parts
C30  ValueDisplayed: 2200pF  [1812]  (hidden comment: C4532X7R3D222K)
C32  ValueDisplayed: 1000pF  [0805_HV]  (hidden comment: 08051C102KAT2A)
C33  ValueDisplayed: 0.1µF  [0805_HV]  (hidden comment: C0805C104K1RACTU)
C34  ValueDisplayed: 0.1µF  [0603]  (hidden comment: C1608X7R1H104K)
C35  ValueDisplayed: 0.022µF  [0603]  (hidden comment: C1608X7R1H223K)
C36  ValueDisplayed: 330pF  [1206]  (hidden comment: GRM31A5C2J331JW01D)
C37  ValueDisplayed: 10µF  [CAPSMT_62_D55]  (hidden comment: EMVE160ADA100MD55G)
C38  ValueDisplayed: 0.22µF  [0805_HV]  (hidden comment: 08053C224KAT2A)
C39  ValueDisplayed: 680pF  [0603]  (hidden comment: C0603C681K5RACTU)
C40  ValueDisplayed: 1µF  [1210]  (hidden comment: C3225X7R2A105K200AA)
C41  ValueDisplayed: 1µF  [1210]  (hidden comment: C3225X7R2A105K200AA)
C42  ValueDisplayed: 22µF  [CAPSMT_62_HA0]  (hidden comment: EMVH630ADA220MHA0G)
C43  ValueDisplayed: 2200pF  [1812]  (hidden comment: C4532X7R3D222K)
C44  ValueDisplayed: 47µF  [SM_RADIAL_C]  (hidden comment: EEE-FK0J470R)
C45  ValueDisplayed: 47µF  [1210]  (hidden comment: GRM32ER61A476KE20L)
C46  ValueDisplayed: 47µF  [1210]  (hidden comment: GRM32ER61A476KE20L)
C47  ValueDisplayed: 1µF  [0805_HV]  (hidden comment: C2012X7R1C105K)
C48  ValueDisplayed: 100pF  [0603]  (hidden comment: 06035A101JAT2A)
C49  ValueDisplayed: 8200pF  [0603]  (hidden comment: GRM188R71H822KA01D)
C50  ValueDisplayed: 0.1µF  [0603]  (hidden comment: EMK107B7104KA-T)
C51  ValueDisplayed: 0.1µF  [0603]  (hidden comment: EMK107B7104KA-T)
C52  ValueDisplayed: 2.2µF  [0603]  (hidden comment: GRM188R61C225KE15D)
C53  ValueDisplayed: 0.01µF  [0805_HV]  (hidden comment: GRM21BR72A103KA01L)
D3  150060GS75000  value Green  [WL-SMCW_GREEN]
D5  SMAJ58A  value 58V  [SMA]
D6  MURA120T3G  [SMA]
D7  BAS16-7-F  [SOT-23]
D8  MBRS540T3G  [SMC]
D9  BAV99,215  [SOT-23]
D10  MURA120T3G  [SMA]
FB1  value 30 ohm  [0805_HV]  (hidden comment: MMZ2012R300A)
FB2  value 30 ohm  [0805_HV]  (hidden comment: MMZ2012R300A)
J7  39357-0002  [Molex_39357-0002]
J8  TSW-102-07-G-S  [TSW-102-07-G-S]
J9  TSW-102-07-G-S  [TSW-102-07-G-S]
L1  ValueDisplayed: 4.7µH  [DO1608C]  (hidden comment: DO1608C-472MLB)
Q1  FDN86246  [SSOT-3]
R25  ValueDisplayed: 330  [0603]  (hidden comment: RC0603JR-07330RL)
R26  ValueDisplayed: 100k  [0402]  (hidden comment: ERJ-2RKF1003X)
R30  ValueDisplayed: 39.2k  [0603]  (hidden comment: CRCW060339K2FKEA)
R31  ValueDisplayed: 392k  [0603]  (hidden comment: CRCW0603392KFKEA)
R32  ValueDisplayed: 59.0k  [0603]  (hidden comment: CRCW060359K0FKEA)
R33  ValueDisplayed: 80.6k  [0603]  (hidden comment: CRCW060380K6FKEA)
R34  ValueDisplayed: 1.27k  [0603]  (hidden comment: CRCW06031K27FKEA)
R35  ValueDisplayed: 24.9k  [0603]  (hidden comment: CRCW060324K9FKEA)
R36  ValueDisplayed: 499  [0603]  (hidden comment: CRCW0603499RFKEA)
R37  ValueDisplayed: 2.0k  [0603]  (hidden comment: CRCW06032K00JNEA)
R38  ValueDisplayed: 49.9  [0603]  (hidden comment: CRCW060349R9FKEA)
R39  ValueDisplayed: 0  [0603]  (hidden comment: CRCW06030000Z0EA)
R40  ValueDisplayed: 0.56  [1206]  (hidden comment: ERJ-8RQFR56V)
R41  ValueDisplayed: 82  [2010]  (hidden comment: CRCW201082R0JNEF)
R42  ValueDisplayed: 49.9  [0603]  (hidden comment: CRCW060349R9FKEA)
R43  ValueDisplayed: 20.0  [1206]  (hidden comment: CRCW120620R0FKEA)
R44  ValueDisplayed: 0  [0603]  (hidden comment: CRCW06030000Z0EA)
R45  ValueDisplayed: 10k  [0603]  (hidden comment: RC0603JR-0710KL)
R46  ValueDisplayed: 665  [0603]  (hidden comment: CRCW0603665RFKEA)
R47  ValueDisplayed: 13.3k  [0603]  (hidden comment: CRCW060313K3FKEA)
R48  ValueDisplayed: 41.2k  [0603]  (hidden comment: CRCW060341K2FKEA)
R49  ValueDisplayed: 19.1k  [0603]  (hidden comment: CRCW060319K1FKEA)
R52  ValueDisplayed: 49.9k  [0805_HV]  (hidden comment: ERJ-6ENF4992V)
T1  ValueDisplayed: 127µH  [XFMR_POE13P]  (hidden comment: POE13P-50L)
TP2  TMS-101-02-T-S  [SAMTEC_TMS-101-02-T-S]
TP3  TMS-101-02-T-S  [SAMTEC_TMS-101-02-T-S]
TP4  TMS-101-02-T-S  [SAMTEC_TMS-101-02-T-S]
TP5  TMS-101-02-T-S  [SAMTEC_TMS-101-02-T-S]
TP6  TMS-101-02-T-S  [SAMTEC_TMS-101-02-T-S]
TP7  TMS-101-02-T-S  [SAMTEC_TMS-101-02-T-S]
TP8  TMS-101-02-T-S  [SAMTEC_TMS-101-02-T-S]
TP9  TMS-101-02-T-S  [SAMTEC_TMS-101-02-T-S]
TP10  TMS-101-02-T-S  [SAMTEC_TMS-101-02-T-S]
TP11  TMS-101-02-T-S  [SAMTEC_TMS-101-02-T-S]
U3  TPS23753APW  [PW0014A_N]
U4  FOD817AS  [N04C]
U5  TLV431ACDBZR  [DBZ0003A_N]
U6  TPS73733DCQR  [DCQ0006A_N]

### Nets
GND: C30.1 C43.1 C44.2(-) C45.2 C46.2 C47.2 C50.2 C51.2 C52.2 R25.2 R47.1 T1.7 T1.8 TP5.1 U5.3(ANODE) U6.3(GND) U6.6(GND)
GNDX: C34.2 C36.2 C37.2(-) C38.2 C40.2 C41.2 C42.2(-) C43.2 J7.1 R30.1 R32.1 R33.1 R40.2 T1.2 TP2.1 TP7.1 U3.6(RTN) U4.3(E)
VCC_3P3: J9.1
VCC_5P0: C50.1 J8.1 R26.1 U6.1(IN)
APD: R30.2 R31.1 U3.12(APD)
POE_NET03: D6.2(A) J7.2 R31.2
POE_NET04: C33.1 C42.1(+) D5.1(K) FB1.2 L1.1 R35.2 U3.8(VDD1) U3.9(VDD)
POE_NET05: C30.2 C40.1 C41.1 C53.1 L1.2 R52.2 T1.3
POE_NET06: Q1.2(S) R39.2 R40.1
POE_NET07: R42.2 T1.1
POE_NET08: D10.2(A) Q1.3(D) R41.2 T1.4 TP8.1
POE_NET09: D7.1(A) R42.1
POE_NET10: C36.1 R41.1
POE_NET11: D8.2(A) R43.1 T1.9 T1.10
POE_NET12: C39.1 C44.1(+) C45.1 C46.1 D8.1(K) J8.2 R44.2 TP4.1
POE_NET13: C39.2 R43.2
POE_NET14: C53.2 D10.1(K) R52.1
POE_NET15: C33.2 D5.2(A) FB2.2 R34.1 TP3.1 U3.7(VSS)
POE_VN: C32.2 FB2.1 ; off-sheet POE_VN
POE_VP: C32.1 D6.1(K) FB1.1 ; off-sheet POE_VP
TRC_001: Q1.1(G) R38.2
TRC_002: R38.1 TP10.1 U3.5(GATE)
NetC34_1: C34.1 R36.2 R37.2 TP9.1 U3.2(VB)
NetC35_1: C35.1 R36.1
NetC35_2: C35.2 R37.1 TP11.1 U3.1(CTL) U4.4(C)
NetC37_1: C37.1(+) C38.1 D7.3(K) TP6.1 U3.4(VC)
NetC47_1: C47.1 D9.3(C) R45.1
NetC48_1: C48.1 C49.1 R47.2 R48.1 U5.1(REF)
NetC48_2: C48.2 D9.1(A) R49.1 U4.2(K) U5.2(CATHODE)
NetC49_2: C49.2 R49.2
NetC51_1: C51.1 U6.4(NR)
NetC52_1: C52.1 D3.2(A) J9.2 U6.2(OUT)
NetD3_1: D3.1(K) R25.1
NetD9_2: D9.2(K) R44.1 R45.2 R46.2 R48.2
NetR26_2: R26.2 U6.5(EN)
NetR32_2: R32.2 U3.14(FRS)
NetR33_2: R33.2 U3.13(BLNK)
NetR34_2: R34.2 U3.11(CLS)
NetR35_1: R35.1 U3.10(DEN)
NetR39_1: R39.1 U3.3(CS)
NetR46_1: R46.1 U4.1(A)

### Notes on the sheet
- (near R52) DNP
- (near D10) DNP

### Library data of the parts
C30 C43 = C4532X7R3D222K: CAP, CERM, 2200 pF, 2000 V, +/- 10%, X7R, 1812; Manufacturer: TDK; Polarized: N; CompType: Capacitor; Value: 2200pF; U/M: EA; Cap_F: 0.0000000022; Tolerance_%: 10; Value1: Unknown; VDC_V: 2000; Value2: 2000V; TaMin_C: -55; TaMax_C: 125; AEC Category: Q200
C32 = 08051C102KAT2A: CAP, CERM, 1000 pF, 100 V, +/- 10%, X7R, 0805; Manufacturer: AVX; Polarized: N; CompType: Capacitor; Value: 1000pF; U/M: EA; Cap_F: 0.000000001; Tolerance_%: 10; ESR_ohm: 0.29; Value1: 0.29 ohm; VDC_V: 100; Value2: 100V; TaMin_C: -55; TaMax_C: 125; Cap_Case: 0805; AEC Category: Q200
C33 = C0805C104K1RACTU: CAP, CERM, 0.1 µF, 100 V, +/- 10%, X7R, 0805; Manufacturer: Kemet; Polarized: N; CompType: Capacitor; Value: 0.1uF; U/M: EA; Cap_F: 0.0000001; Tolerance_%: 10; ESR_ohm: 0.064; Value1: 0.064 ohm; VDC_V: 100; Value2: 100V; IRMS_A: 1.64; TaMin_C: -55; TaMax_C: 125; Cap_Case: 0805; AEC Category: Q200
C34 = C1608X7R1H104K: CAP, CERM, 0.1 µF, 50 V, +/- 10%, X7R, 0603; Manufacturer: TDK; Polarized: N; CompType: Capacitor; Value: 0.1uF; U/M: EA; Cap_F: 0.0000001; Tolerance_%: 10; ESR_ohm: 0.017; Value1: 0.017 ohm; VDC_V: 50; Value2: 50V; TaMin_C: -55; TaMax_C: 125; AEC Category: Q200
C35 = C1608X7R1H223K: CAP, CERM, 0.022 µF, 50 V, +/- 10%, X7R, 0603; Manufacturer: TDK; Polarized: N; CompType: Capacitor; Value: 0.022uF; U/M: EA; Cap_F: 0.000000022; Tolerance_%: 10; ESR_ohm: 0.0383; Value1: 0.0383 ohm; VDC_V: 50; Value2: 50V; TaMin_C: -55; TaMax_C: 125; AEC Category: Q200
C36 = GRM31A5C2J331JW01D: CAP, CERM, 330 pF, 630 V, +/- 5%, C0G/NP0, 1206; Manufacturer: MuRata; Polarized: N; CompType: Capacitor; Value: 330pF; U/M: EA; Cap_F: 0.00000000033; Tolerance_%: 5; Value1: Unknown; VDC_V: 630; Value2: 630V; TaMin_C: -55; TaMax_C: 125; AEC Category: Q200
C37 = EMVE160ADA100MD55G: CAP, AL, 10 µF, 16 V, +/- 20%, SMD; Manufacturer: Chemi-Con; Polarized: Y; CompType: Capacitor; Value: 10uF; U/M: EA; Cap_F: 0.00001; Tolerance_%: 20; Value1: Unknown; VDC_V: 16; Value2: 16V; IRMS_A: 0.017; TaMin_C: -40; TaMax_C: 105; Cap_Case: D55; AEC Category: Q200
C38 = 08053C224KAT2A: CAP, CERM, 0.22 µF, 25 V, +/- 10%, X7R, 0805; Manufacturer: AVX; Polarized: N; CompType: Capacitor; Value: 0.22uF; U/M: EA; Cap_F: 0.00000022; Tolerance_%: 10; ESR_ohm: 0.016; Value1: 0.016 ohm; VDC_V: 25; Value2: 25V; TaMin_C: -55; TaMax_C: 125; Cap_Case: 0805; AEC Category: Q200
C39 = C0603C681K5RACTU: CAP, CERM, 680 pF, 50 V, +/- 10%, X7R, 0603; Manufacturer: Kemet; Polarized: N; CompType: Capacitor; Value: 680pF; U/M: EA; Cap_F: 0.00000000068; Tolerance_%: 10; Value1: Unknown; VDC_V: 50; Value2: 50V; TaMin_C: -55; TaMax_C: 125; AEC Category: Q200
C40 C41 = C3225X7R2A105K200AA: CAP, CERM, 1 µF, 100 V, +/- 10%, X7R, 1210; Manufacturer: TDK; Polarized: N; CompType: Capacitor; Value: 1uF; U/M: EA; Cap_F: 0.000001; Tolerance_%: 10; Value1: Unknown; VDC_V: 100; Value2: 100V; TaMin_C: -55; TaMax_C: 125; AEC Category: Q200
C42 = EMVH630ADA220MHA0G: CAP, AL, 22 µF, 63 V, +/- 20%, 0.7 ohm, SMD; Manufacturer: Chemi-Con; Polarized: Y; CompType: Capacitor; Value: 22uF; U/M: EA; Cap_F: 0.000022; Tolerance_%: 20; Value1: 0.7 ohm; VDC_V: 63; Value2: 63V; ESR_ohm: 0.7; IRMS_A: 0.1; TaMin_C: -40; TaMax_C: 125; Cap_Case: HA0; AEC Category: Q200
C44 = EEE-FK0J470R: CAP, AL, 47 µF, 6.3 V, +/- 20%, 0.7 ohm, SMD; Manufacturer: Panasonic; Polarized: Y; CompType: Capacitor; Value: 47uF; U/M: EA; Cap_F: 0.000047; Tolerance_%: 20; Value1: 0.7 ohm; VDC_V: 6.3; Value2: 6.3V; ESR_ohm: 0.7; IRMS_A: 0.16; TaMin_C: -55; TaMax_C: 105; Cap_Case: C; AEC Category: Q200
C45 C46 = GRM32ER61A476KE20L: CAP, CERM, 47 µF, 10 V, +/- 10%, X5R, 1210; Manufacturer: MuRata; Polarized: N; CompType: Capacitor; Value: 47uF; U/M: EA; Cap_F: 0.000047; Tolerance_%: 10; ESR_ohm: 0.001; Value1: 0.001 ohm; Value2: 10V; TaMin_C: -55; TaMax_C: 85; AEC Category: Q200
C47 = C2012X7R1C105K: CAP, CERM, 1 µF, 16 V, +/- 10%, X7R, 0805; Manufacturer: TDK; Polarized: N; CompType: Capacitor; Value: 1uF; U/M: EA; Cap_F: 0.000001; Tolerance_%: 10; ESR_ohm: 0.0075; Value1: 0.0075 ohm; VDC_V: 16; Value2: 16V; TaMin_C: -55; TaMax_C: 125; Cap_Case: 0805; AEC Category: Q200
C48 = 06035A101JAT2A: CAP, CERM, 100 pF, 50 V, +/- 5%, C0G/NP0, 0603; Manufacturer: AVX; Polarized: N; CompType: Capacitor; Value: 100pF; U/M: EA; Cap_F: 0.0000000001; Tolerance_%: 5; ESR_ohm: 0.119; Value1: 0.119 ohm; VDC_V: 50; Value2: 50V; TaMin_C: -55; TaMax_C: 125; AEC Category: Q200
C49 = GRM188R71H822KA01D: CAP, CERM, 8200 pF, 50 V, +/- 10%, X7R, 0603; Manufacturer: MuRata; Polarized: N; CompType: Capacitor; Value: 8200pF; U/M: EA; Cap_F: 0.0000000082; Tolerance_%: 10; Value1: Unknown; VDC_V: 50; Value2: 50V; TaMin_C: -55; TaMax_C: 125; AEC Category: Q200
C50 C51 = EMK107B7104KA-T: CAP, CERM, 0.1 µF, 16 V, +/- 10%, X7R, 0603; Manufacturer: Taiyo Yuden; Polarized: N; CompType: Capacitor; Value: 0.1uF; U/M: EA; Cap_F: 0.0000001; Tolerance_%: 10; Value1: Unknown; VDC_V: 16; Value2: 16V; TaMin_C: -55; TaMax_C: 125; AEC Category: Q200
C52 = GRM188R61C225KE15D: CAP, CERM, 2.2 µF, 16 V, +/- 10%, X5R, 0603; Manufacturer: MuRata; Polarized: N; CompType: Capacitor; Value: 2.2uF; U/M: EA; Cap_F: 0.0000022; Tolerance_%: 10; Value1: Unknown; VDC_V: 16; Value2: 16V; TaMin_C: -55; TaMax_C: 85; AEC Category: Q200
C53 = GRM21BR72A103KA01L: CAP, CERM, 0.01 µF, 100 V, +/- 10%, X7R, 0805; Manufacturer: MuRata; Polarized: N; CompType: Capacitor; Value: 0.01uF; U/M: EA; Cap_F: 0.00000001; Tolerance_%: 10; Value1: Unknown; VDC_V: 100; Value2: 100V; TaMin_C: -55; TaMax_C: 125; Cap_Case: 0805; AEC Category: Q200
D3 = 150060GS75000: LED, Green, SMD; Manufacturer: Wurth Elektronik; Type: InGaN; Vf_V: 3.2; Value2: 3.2V; Io_A: 0.02; Tjmax_C: 85; Value1: W; Angle: 140; U/M: EA
D5 = SMAJ58A: Diode, TVS, Uni, 58 V, 400 W, SMA; Manufacturer: Diodes Inc.; U/M: EA; Power_W: 400; Vr_V: 58; Value1: 400W; AEC Category: Q101
D6 D10 = MURA120T3G: Diode, Ultrafast, 200 V, 1 A, SMA; Manufacturer: ON Semiconductor; U/M: EA; Vf_V: 0.0875; Value: 200V; Value1: 1A; Value2: 0.0875V; Io_A: 1; Vr_V: 200; TJmax_C: 175; AEC Category: Q101
D7 = BAS16-7-F: Diode, Ultrafast, 75 V, 0.3 A, SOT-23; Manufacturer: Diodes Inc.; U/M: EA; Vf_V: 1.125; Value: 75V; Value1: 0.3A; Value2: 1.125V; Io_A: 0.3; Vr_V: 75; AEC Category: Q101
D8 = MBRS540T3G: Diode, Schottky, 40 V, 5 A, SMC; Manufacturer: ON Semiconductor; U/M: EA; Vf_V: 0.5; Value: 40V; Value1: 5A; Value2: 0.5V; Io_A: 5; Vr_V: 40; TJmax_C: 150; RJC_CperW: 12; AEC Category: Q101
D9 = BAV99,215: Diode, Switching, 100 V, 0.215 A, SOT-23; Manufacturer: NXP Semiconductor; U/M: EA; Vf_V: 1.25; Value: 100V; Value1: 0.215A; Value2: 1.25V; Io_A: 0.215; Vr_V: 100; TJmax_C: 150; AEC Category: Q101
FB1 FB2 = MMZ2012R300A: Ferrite Bead, 30 ohm @ 100 MHz, 1.5 A, 0805; Manufacturer: TDK; Imax_A: 1.5; DCR_ohm: 0.05; Value1: 0.05 ohm; Value2: 1.5A; ZTyp@100MHz_Ohm: 30
J7 = 39357-0002: Terminal Block, 3.5 mm, 2x1, Tin, TH; Manufacturer: Molex; SymbolCreator: a0412235
J8 J9 = TSW-102-07-G-S: as J10 on sheet TIDM_TM4C129POE_Ethernet
L1 = DO1608C-472MLB: Inductor, Drum Core, Ferrite, 4.7 µH, 1.5 A, 0.09 ohm, SMD; Manufacturer: Coilcraft; Value: 4.7uH; Ind_H: 4.7E-6; Imax_A: 1.5; Irms: 1.9A @ 15C rise; Isat: 1.5A @ 10% inductance drop; DCR_ohm: 0.09; Value2: 1.5A; AEC Category: Q200
Q1 = FDN86246: MOSFET, N-CH, 150 V, 1.6 A, SSOT-3; Manufacturer: Fairchild Semiconductor; Alternate Manufacturer: None; U/M: EA; ChType: N; Value: 150V; VdsMax_V: 150; Value1: ? ohm; Value2: 2.9 nC; QgTyp_nC: 2.9; Vgs_V: 20; IdsMax_A: 1.6; AEC Category: Q101
R25 = RC0603JR-07330RL: as R27 on sheet TIDM_TM4C129POE_Connector
R26 = ERJ-2RKF1003X: RES, 100 k, 1%, 0.1 W, 0402; Manufacturer: Panasonic; CompType: Resistor; Value: 100k; Res_ohm: 100000; Tolerance_%: 1; Power_W: 0.1; Value2: 0.1W; VDC_V: 50; TempCo: 100 ppm/C; EIA_Code: E96; U/M: EA; AEC Category: Q200
R30 = CRCW060339K2FKEA: RES, 39.2 k, 1%, 0.1 W, 0603; Manufacturer: Vishay-Dale; CompType: Resistor; Value: 39.2k; Res_ohm: 39200; Value_Code: 39k2; Tolerance_%: 1; Power_W: 0.1; Value2: 0.1W; VDC_V: 75; TempCo: 100 ppm/C; EIA_Code: E96; U/M: EA; AEC Category: Q200
R31 = CRCW0603392KFKEA: RES, 392 k, 1%, 0.1 W, 0603; Manufacturer: Vishay-Dale; CompType: Resistor; Value: 392k; Res_ohm: 392000; Tolerance_%: 1; Power_W: 0.1; Value2: 0.1W; VDC_V: 75; TempCo: 100 ppm/C; EIA_Code: E96; U/M: EA; AEC Category: Q200
R32 = CRCW060359K0FKEA: RES, 59.0 k, 1%, 0.1 W, 0603; Manufacturer: Vishay-Dale; CompType: Resistor; Value: 59.0k; Res_ohm: 59000; Value_Code: 59k0; Tolerance_%: 1; Power_W: 0.1; Value2: 0.1W; VDC_V: 75; TempCo: 100 ppm/C; EIA_Code: E96; U/M: EA; AEC Category: Q200
R33 = CRCW060380K6FKEA: RES, 80.6 k, 1%, 0.1 W, 0603; Manufacturer: Vishay-Dale; CompType: Resistor; Value: 80.6k; Res_ohm: 80600; Value_Code: 80k6; Tolerance_%: 1; Power_W: 0.1; Value2: 0.1W; VDC_V: 75; TempCo: 100 ppm/C; EIA_Code: E96; U/M: EA; AEC Category: Q200
R34 = CRCW06031K27FKEA: RES, 1.27 k, 1%, 0.1 W, 0603; Manufacturer: Vishay-Dale; CompType: Resistor; Value: 1.27k; Res_ohm: 1270; Value_Code: 1k27; Tolerance_%: 1; Power_W: 0.1; Value2: 0.1W; VDC_V: 75; TempCo: 100 ppm/C; EIA_Code: E96; U/M: EA; AEC Category: Q200
R35 = CRCW060324K9FKEA: RES, 24.9 k, 1%, 0.1 W, 0603; Manufacturer: Vishay-Dale; CompType: Resistor; Value: 24.9k; Res_ohm: 24900; Value_Code: 24k9; Tolerance_%: 1; Power_W: 0.1; Value2: 0.1W; VDC_V: 75; TempCo: 100 ppm/C; EIA_Code: E96; U/M: EA; AEC Category: Q200
R36 = CRCW0603499RFKEA: RES, 499, 1%, 0.1 W, 0603; Manufacturer: Vishay-Dale; CompType: Resistor; Value: 499; Value_Code: 499R; Tolerance_%: 1; Power_W: 0.1; Value2: 0.1W; VDC_V: 75; TempCo: 100 ppm/C; EIA_Code: E96; U/M: EA; AEC Category: Q200
R37 = CRCW06032K00JNEA: RES, 2.0 k, 5%, 0.1 W, 0603; Manufacturer: Vishay-Dale; CompType: Resistor; Value: 2.0k; Res_ohm: 2000; Value_Code: 2k00; Tolerance_%: 5; Power_W: 0.1; Value2: 0.1W; VDC_V: 75; TempCo: 200 ppm/C; EIA_Code: E24; U/M: EA; AEC Category: Q200
R38 R42 = CRCW060349R9FKEA: RES, 49.9, 1%, 0.1 W, 0603; Manufacturer: Vishay-Dale; CompType: Resistor; Value: 49.9; Value_Code: 49R9; Tolerance_%: 1; Power_W: 0.1; Value2: 0.1W; VDC_V: 75; TempCo: 100 ppm/C; EIA_Code: E96; U/M: EA; AEC Category: Q200
R39 R44 = CRCW06030000Z0EA: RES, 0, 5%, 0.1 W, 0603; Manufacturer: Vishay-Dale; CompType: Resistor; Value: 0; Value_Code: 0000; Tolerance_%: 5; Power_W: 0.1; Value2: 0.1W; VDC_V: 75; TempCo: 200 ppm/C; EIA_Code: E24; U/M: EA; AEC Category: Q200
R40 = ERJ-8RQFR56V: RES, 0.56, 1%, 0.25 W, 1206; Manufacturer: Panasonic; CompType: Resistor; Value: 0.56; Value_Code: R560; Tolerance_%: 1; Power_W: 0.25; Value2: 0.25W; TempCo: 250 ppm/C; EIA_Code: E96; U/M: EA; AEC Category: Q200
R41 = CRCW201082R0JNEF: RES, 82, 5%, 0.75 W, 2010; Manufacturer: Vishay-Dale; CompType: Resistor; Value: 82; Value_Code: 82R0; Tolerance_%: 5; Power_W: 0.75; Value2: 0.75W; VDC_V: 400; TempCo: 200 ppm/C; EIA_Code: E24; U/M: EA; AEC Category: Q200
R43 = CRCW120620R0FKEA: RES, 20.0, 1%, 0.25 W, 1206; Manufacturer: Vishay-Dale; CompType: Resistor; Value: 20.0; Res_ohm: 20; Value_Code: 20R0; Tolerance_%: 1; Power_W: 0.25; Value2: 0.25W; VDC_V: 200; TempCo: 100 ppm/C; EIA_Code: E96; U/M: EA; AEC Category: Q200
R45 = RC0603JR-0710KL: RES, 10 k, 5%, 0.1 W, 0603; Manufacturer: Yageo America; CompType: Resistor; Value: 10k; Res_ohm: 10000; Value_Code: 10k0; Tolerance_%: 5; Power_W: 0.1; Value2: 0.1W; VDC_V: 50; TempCo: 100 ppm/C; EIA_Code: E24; U/M: EA; AEC Category: Q200
R46 = CRCW0603665RFKEA: RES, 665, 1%, 0.1 W, 0603; Manufacturer: Vishay-Dale; CompType: Resistor; Value: 665; Value_Code: 665R; Tolerance_%: 1; Power_W: 0.1; Value2: 0.1W; VDC_V: 75; TempCo: 100 ppm/C; EIA_Code: E96; U/M: EA; AEC Category: Q200
R47 = CRCW060313K3FKEA: RES, 13.3 k, 1%, 0.1 W, 0603; Manufacturer: Vishay-Dale; CompType: Resistor; Value: 13.3k; Res_ohm: 13300; Value_Code: 13k3; Tolerance_%: 1; Power_W: 0.1; Value2: 0.1W; VDC_V: 75; TempCo: 100 ppm/C; EIA_Code: E96; U/M: EA; AEC Category: Q200
R48 = CRCW060341K2FKEA: RES, 41.2 k, 1%, 0.1 W, 0603; Manufacturer: Vishay-Dale; CompType: Resistor; Value: 41.2k; Res_ohm: 41200; Value_Code: 41k2; Tolerance_%: 1; Power_W: 0.1; Value2: 0.1W; VDC_V: 75; TempCo: 100 ppm/C; EIA_Code: E96; U/M: EA; AEC Category: Q200
R49 = CRCW060319K1FKEA: RES, 19.1 k, 1%, 0.1 W, 0603; Manufacturer: Vishay-Dale; CompType: Resistor; Value: 19.1k; Res_ohm: 19100; Value_Code: 19k1; Tolerance_%: 1; Power_W: 0.1; Value2: 0.1W; VDC_V: 75; TempCo: 100 ppm/C; EIA_Code: E96; U/M: EA; AEC Category: Q200
R52 = ERJ-6ENF4992V: RES, 49.9 k, 1%, 0.125 W, 0805; Manufacturer: Panasonic; CompType: Resistor; Value: 49.9k; Res_ohm: 49900; Value_Code: 49k9; Tolerance_%: 1; Power_W: 0.125; Value2: 0.125W; TempCo: 100 ppm/C; EIA_Code: E96; U/M: EA; AEC Category: Q200
T1 = POE13P-50L: Flyback Transfomer, 13W, SMD; Manufacturer: Coilcraft; SymbolCreator: a0412235; Value: 127uH; Lp: 127; LeakageL: 0.95; CompType: Transformer
TP2-TP11 = TMS-101-02-T-S: as TP1 on sheet TIDM_TM4C129POE_Micro
U3 = TPS23753APW: IEEE 802.3-2005 PoE Interface and Isolated Converter Controller with Enhanced ESD Ride-Through, -40 to 125 degC, 14-pin SOP (PW14), Green (RoHS & no Sb/Br); Manufacturer: Texas Instruments; Alternate PartNumber: Equivalent; Auxiliary Power Rails Supported: 12V-57V; Auxiliary/Local Power Support: Programmable; Duty Cycle(%): 78; Fault Response: Auto Retry; PD Power Level: 13W; PoE Current Limit(Min)(mA): 405; PoE I/F & DC DC Control: TRUE; PoE Inrush Limit(Typ)(mA): 140; PoE Standards Supported: 802.3at type1; rDS(on) per FET(Typ)(mOhms): 700; SubFamily: Powered Device; Switching Frequency: Synchronizable and Programmable; UVLO: Unified
U4 = FOD817AS: Optocoupler, 5 kV, 80-160% CTR, SMT; Manufacturer: Fairchild Semiconductor; CTR (Min): 80%; CTR (Max): 160%; Voltage_Isolation_Vrms: 5000V
U5 = TLV431ACDBZR: Low Voltage Adjustable Precision Shunt Regulator, 39 ppm / degC, 15 mA, 0 to 70 degC, 3-pin SOT-23 (DBZ), Green (RoHS & no Sb/Br); Manufacturer: Texas Instruments; Alternate PartNumber: Equivalent; Iout/Iz(Max)(mA): 15; Min Iz for Regulation(uA): 80; Rating: Catalog; SubFamily: Shunt Voltage Reference; Temp Coeff(Max)(ppm/ degree C): 129; Temp Coeff(Typ)(ppm/ degree C): 39; VO Adj(Max)(V): 6; VO Adj(Min)(V): 1.24
U6 = TPS73733DCQR: Single Output LDO, 1 A, Fixed 3.3 V Output, 2.2 to 5.5 V Input, with Reverse Current Protection, 6-pin SOT-223 (DCQ), -40 to 125 degC, Green (RoHS & no Sb/Br); Manufacturer: Texas Instruments; Alternate PartNumber: Equivalent; Accuracy(%): 3; Fixed Output Options(V): 3.3; Iout(Max)(A): 1; Iq(Typ)(mA): 0.3; Rating: Catalog; SubFamily: Single Channel LDO; Vdo(Typ)(mV): 130; Vin(Max)(V): 5.5; Vin(Min)(V): 2.2

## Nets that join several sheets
GND: TIDM_TM4C129POE_Micro (39 pins), TIDM_TM4C129POE_Connector (15 pins), TIDM_TM4C129POE_Ethernet (9 pins), TIDM_TM4C129POE_PowerStage (17 pins)
VCC_3P3: TIDM_TM4C129POE_Micro (35 pins), TIDM_TM4C129POE_Connector (5 pins), TIDM_TM4C129POE_Ethernet (10 pins), TIDM_TM4C129POE_PowerStage (J9.1)
VCC_5P0: TIDM_TM4C129POE_Micro (J1A.2 J2A.2), TIDM_TM4C129POE_PowerStage (C50.1 J8.1 R26.1 U6.1)
ENETLED0: TIDM_TM4C129POE_Micro (U1.42), TIDM_TM4C129POE_Ethernet (J6.11)
ENETLED1: TIDM_TM4C129POE_Micro (U1.46), TIDM_TM4C129POE_Ethernet (J6.13)
EPHYRX_N: TIDM_TM4C129POE_Micro (U1.53), TIDM_TM4C129POE_Ethernet (D4.1 D4.8 J6.6 R21.1)
EPHYRX_P: TIDM_TM4C129POE_Micro (U1.54), TIDM_TM4C129POE_Ethernet (D4.2 D4.7 J6.3 R22.1)
EPHYTX_N: TIDM_TM4C129POE_Micro (U1.56), TIDM_TM4C129POE_Ethernet (D4.3 D4.6 J6.2 R23.1)
EPHYTX_P: TIDM_TM4C129POE_Micro (U1.57), TIDM_TM4C129POE_Ethernet (D4.4 D4.5 J6.1 R24.1)
GPIOSW1: TIDM_TM4C129POE_Micro (U1.107), TIDM_TM4C129POE_Connector (C23.1 R8.1 R9.1)
GPIOSW2: TIDM_TM4C129POE_Micro (U1.108), TIDM_TM4C129POE_Connector (C24.1 R10.1 R11.1)
GPLED0: TIDM_TM4C129POE_Micro (U1.116), TIDM_TM4C129POE_Connector (D1.2)
GPLED1: TIDM_TM4C129POE_Micro (U1.117), TIDM_TM4C129POE_Connector (D2.2)
JTAG_TCK: TIDM_TM4C129POE_Micro (U1.100), TIDM_TM4C129POE_Connector (R14.2 R18.1)
JTAG_TDI: TIDM_TM4C129POE_Micro (U1.98), TIDM_TM4C129POE_Connector (R16.2)
JTAG_TDO: TIDM_TM4C129POE_Micro (U1.97), TIDM_TM4C129POE_Connector (R15.2 R19.2)
JTAG_TMS: TIDM_TM4C129POE_Micro (U1.99), TIDM_TM4C129POE_Connector (R13.2 R17.1)
POE_VN: TIDM_TM4C129POE_Ethernet (J10.1), TIDM_TM4C129POE_PowerStage (C32.2 FB2.1)
POE_VP: TIDM_TM4C129POE_Ethernet (J11.2), TIDM_TM4C129POE_PowerStage (C32.1 D6.1 FB1.1)
RST_N: TIDM_TM4C129POE_Micro (6 pins), TIDM_TM4C129POE_Connector (J4.10)
UART0RX: TIDM_TM4C129POE_Micro (U1.33), TIDM_TM4C129POE_Connector (J5.2)
UART0TX: TIDM_TM4C129POE_Micro (U1.34), TIDM_TM4C129POE_Connector (J5.1)
USBD_N: TIDM_TM4C129POE_Micro (U1.93), TIDM_TM4C129POE_Connector (J3.2 U2.2 U2.5)
USBD_P: TIDM_TM4C129POE_Micro (U1.94), TIDM_TM4C129POE_Connector (J3.3 U2.3)

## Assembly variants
001: not fitted FID1 FID2 FID3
